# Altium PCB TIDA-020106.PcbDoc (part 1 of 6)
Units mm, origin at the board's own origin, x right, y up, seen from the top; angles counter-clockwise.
Board outline 158.53 x 83.25 mm, 6 copper layers (Top Layer, GND, Power, Sig4, GND (Mid4), Bottom Layer), stack 1.59 mm thick; 410 components, 255 nets, 1280 pads, 2405 vias.
Unrouted connection lines stored in the file: 294.
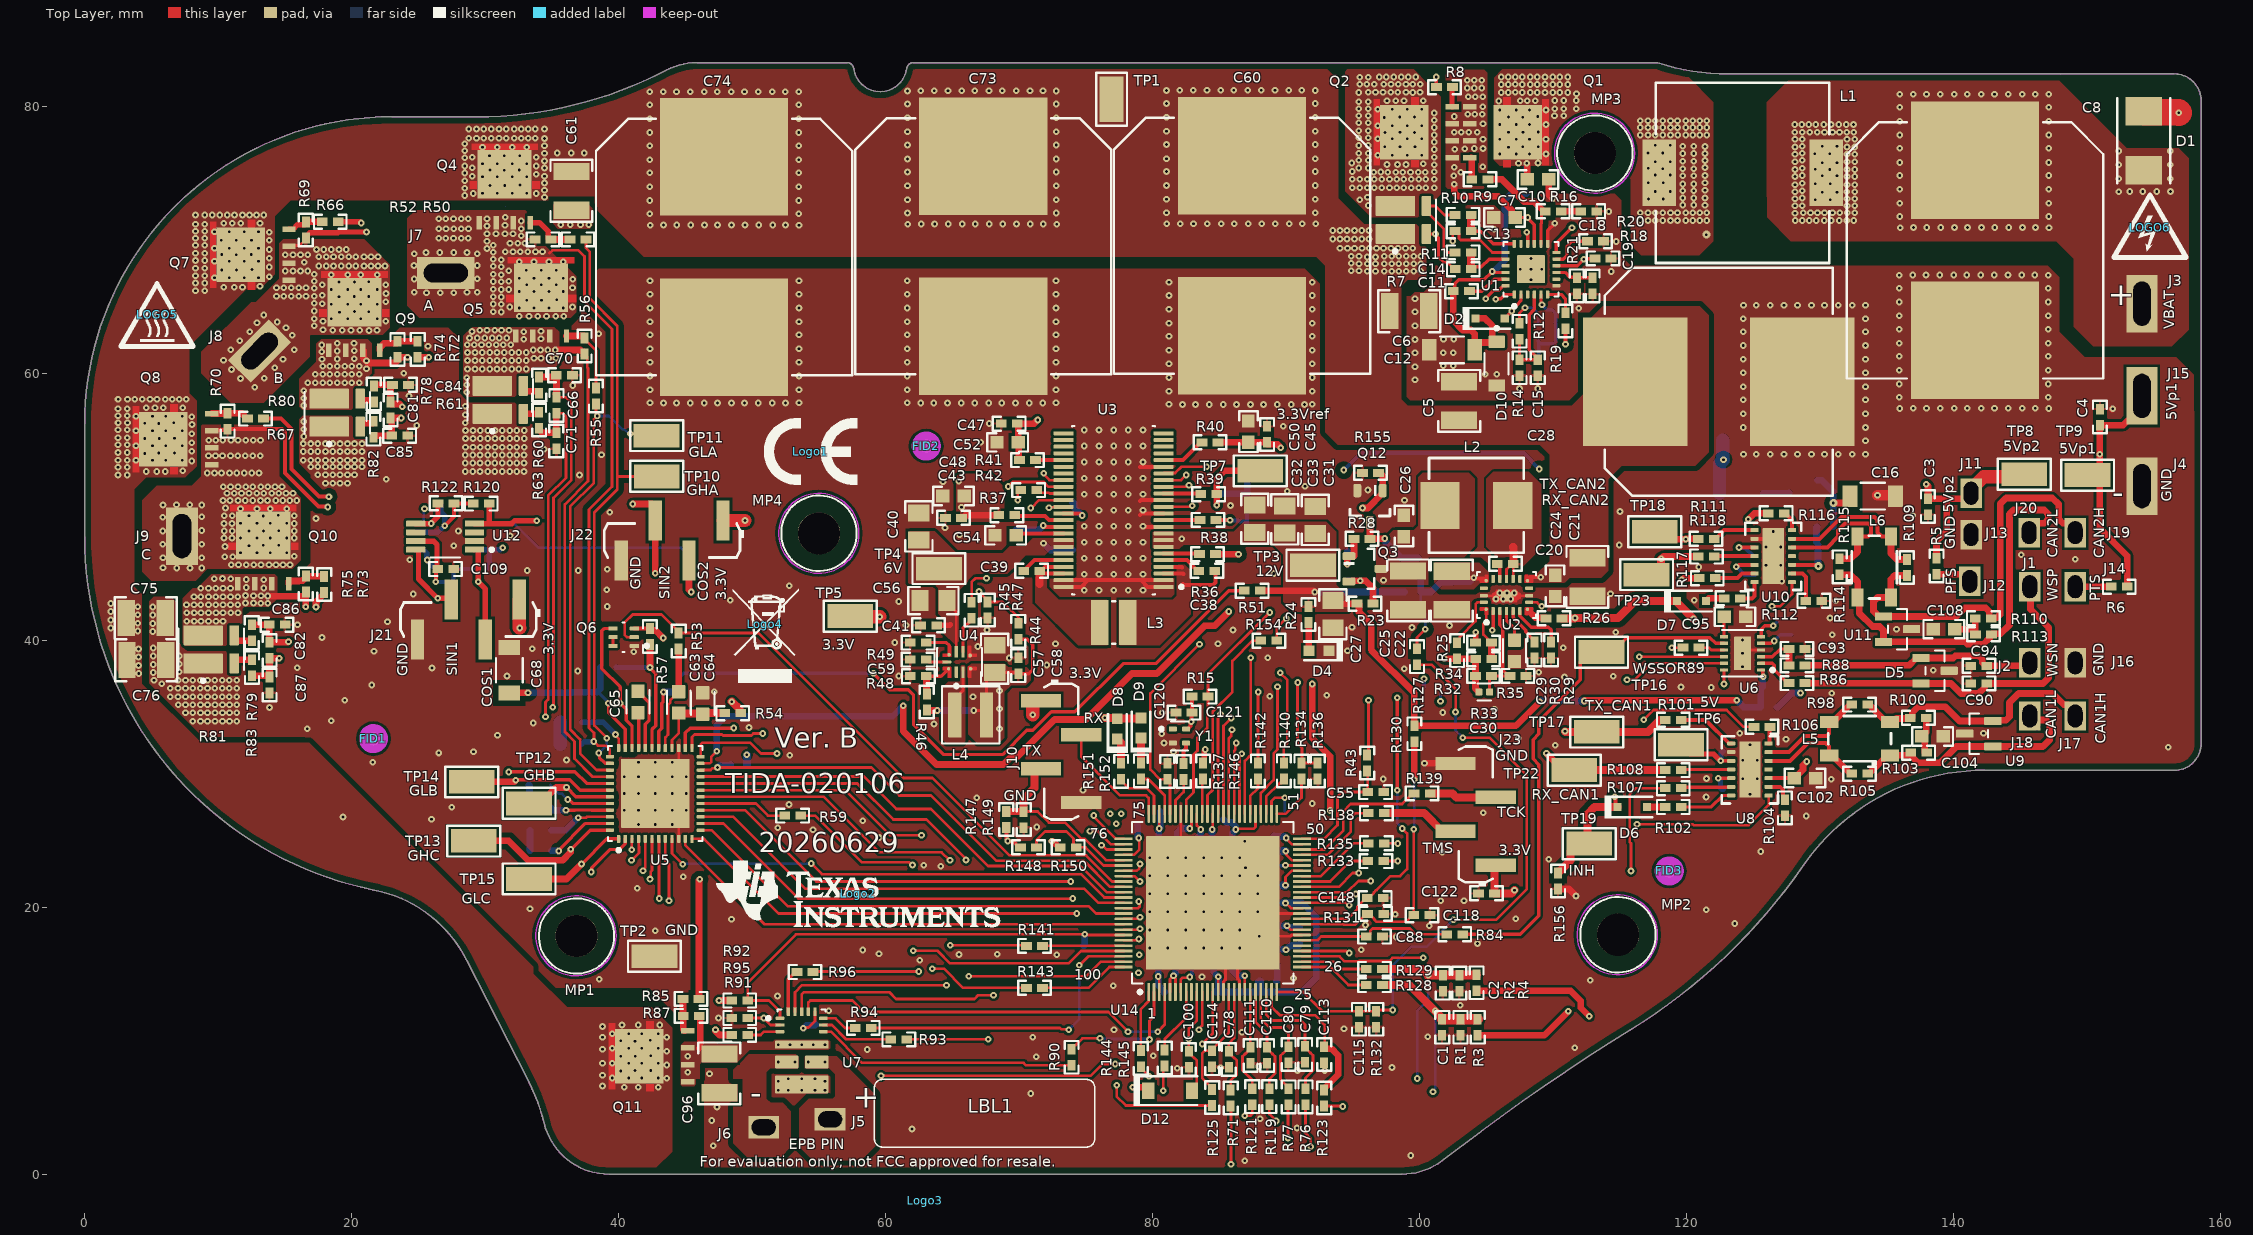
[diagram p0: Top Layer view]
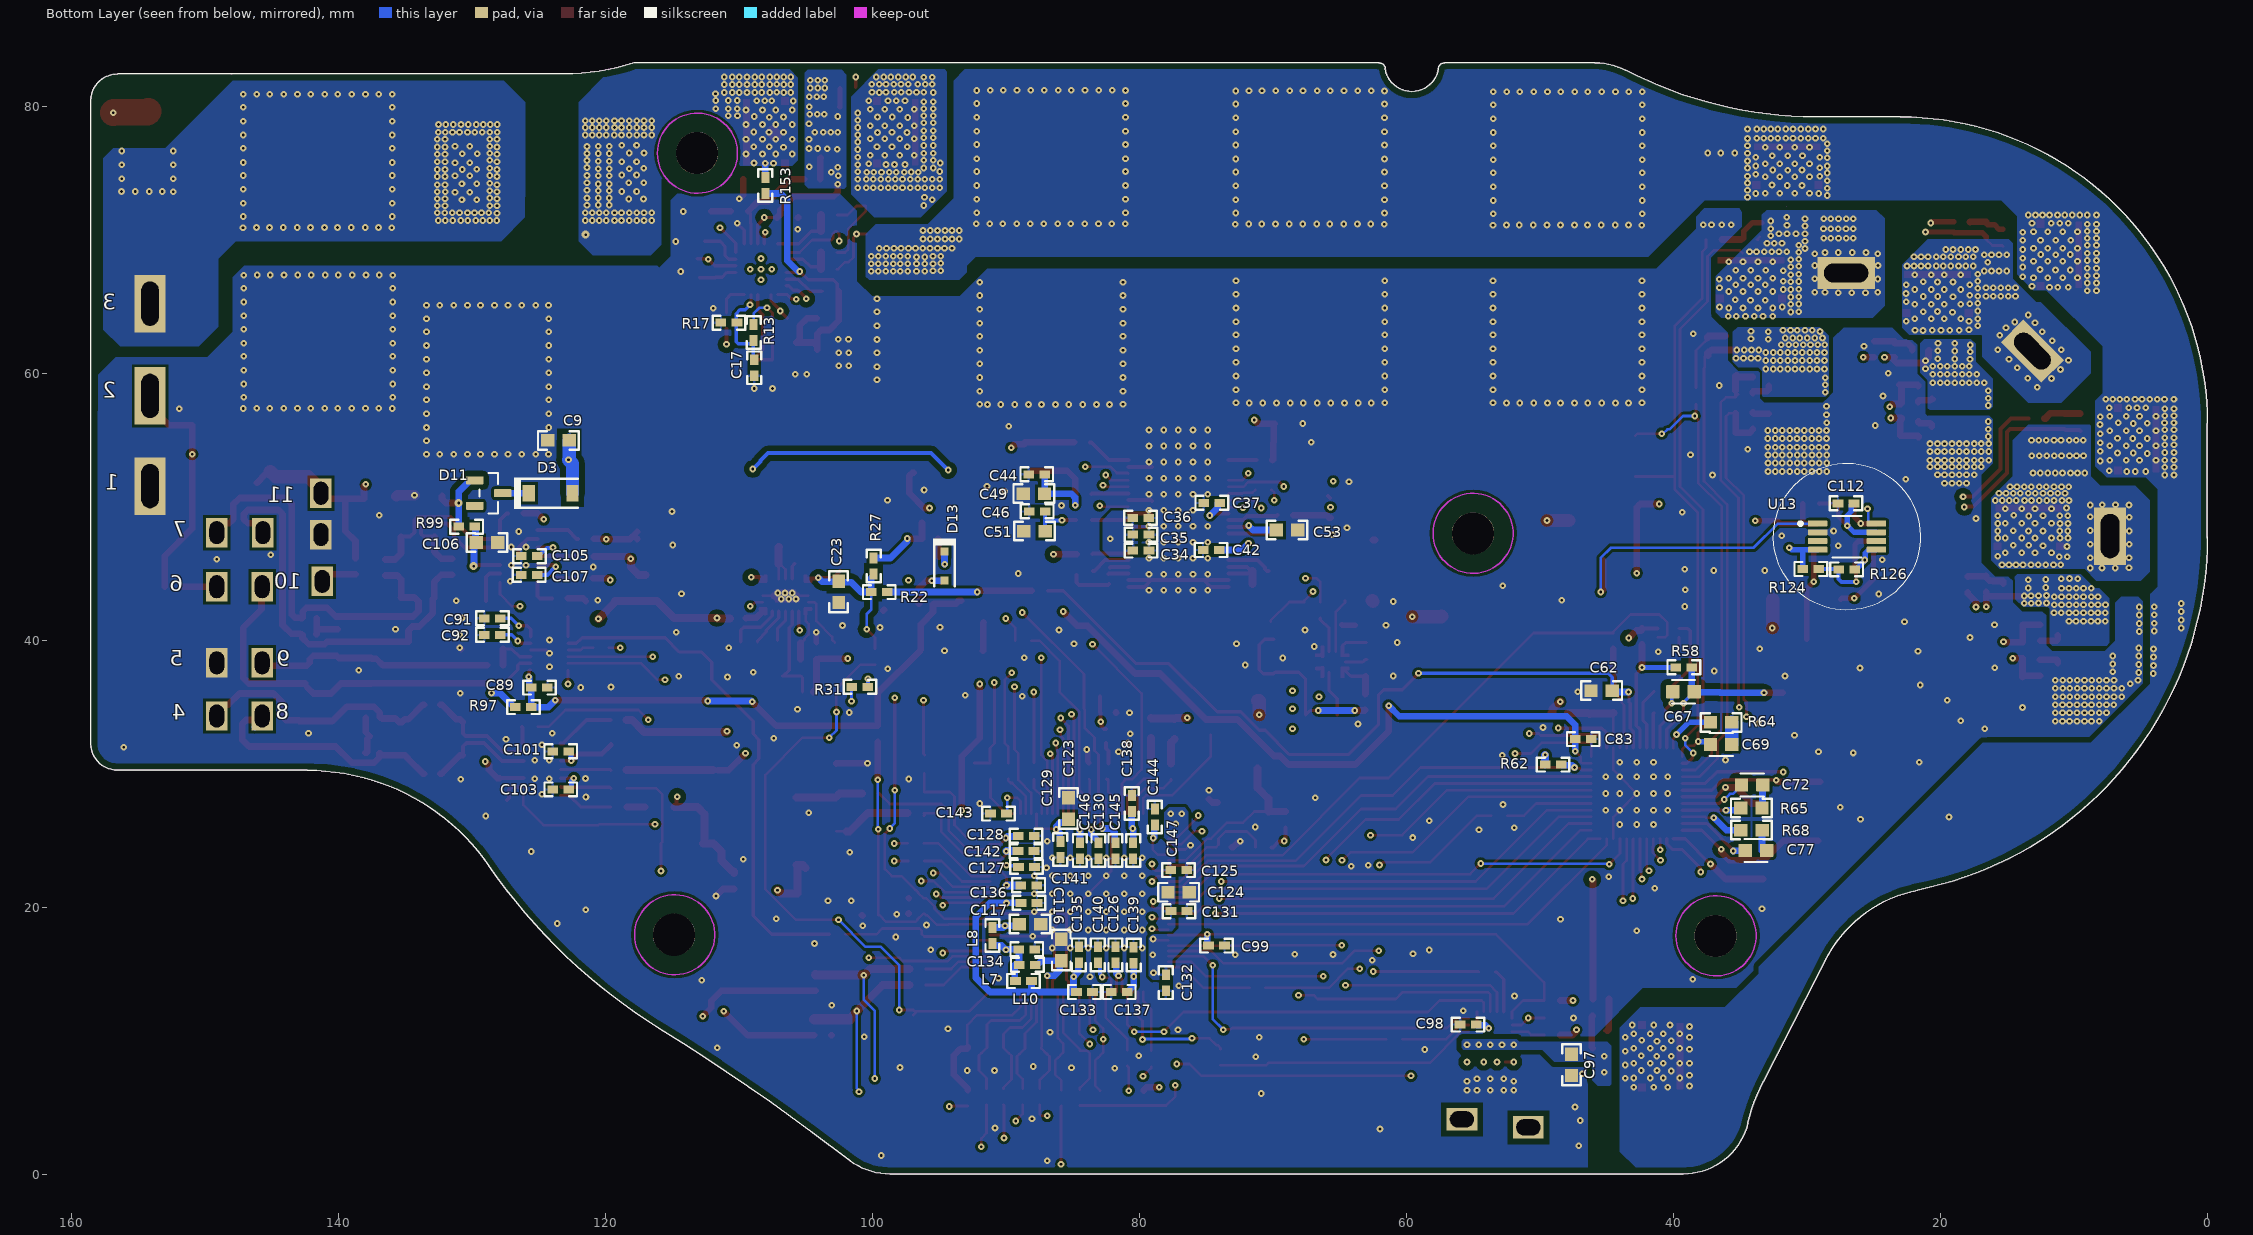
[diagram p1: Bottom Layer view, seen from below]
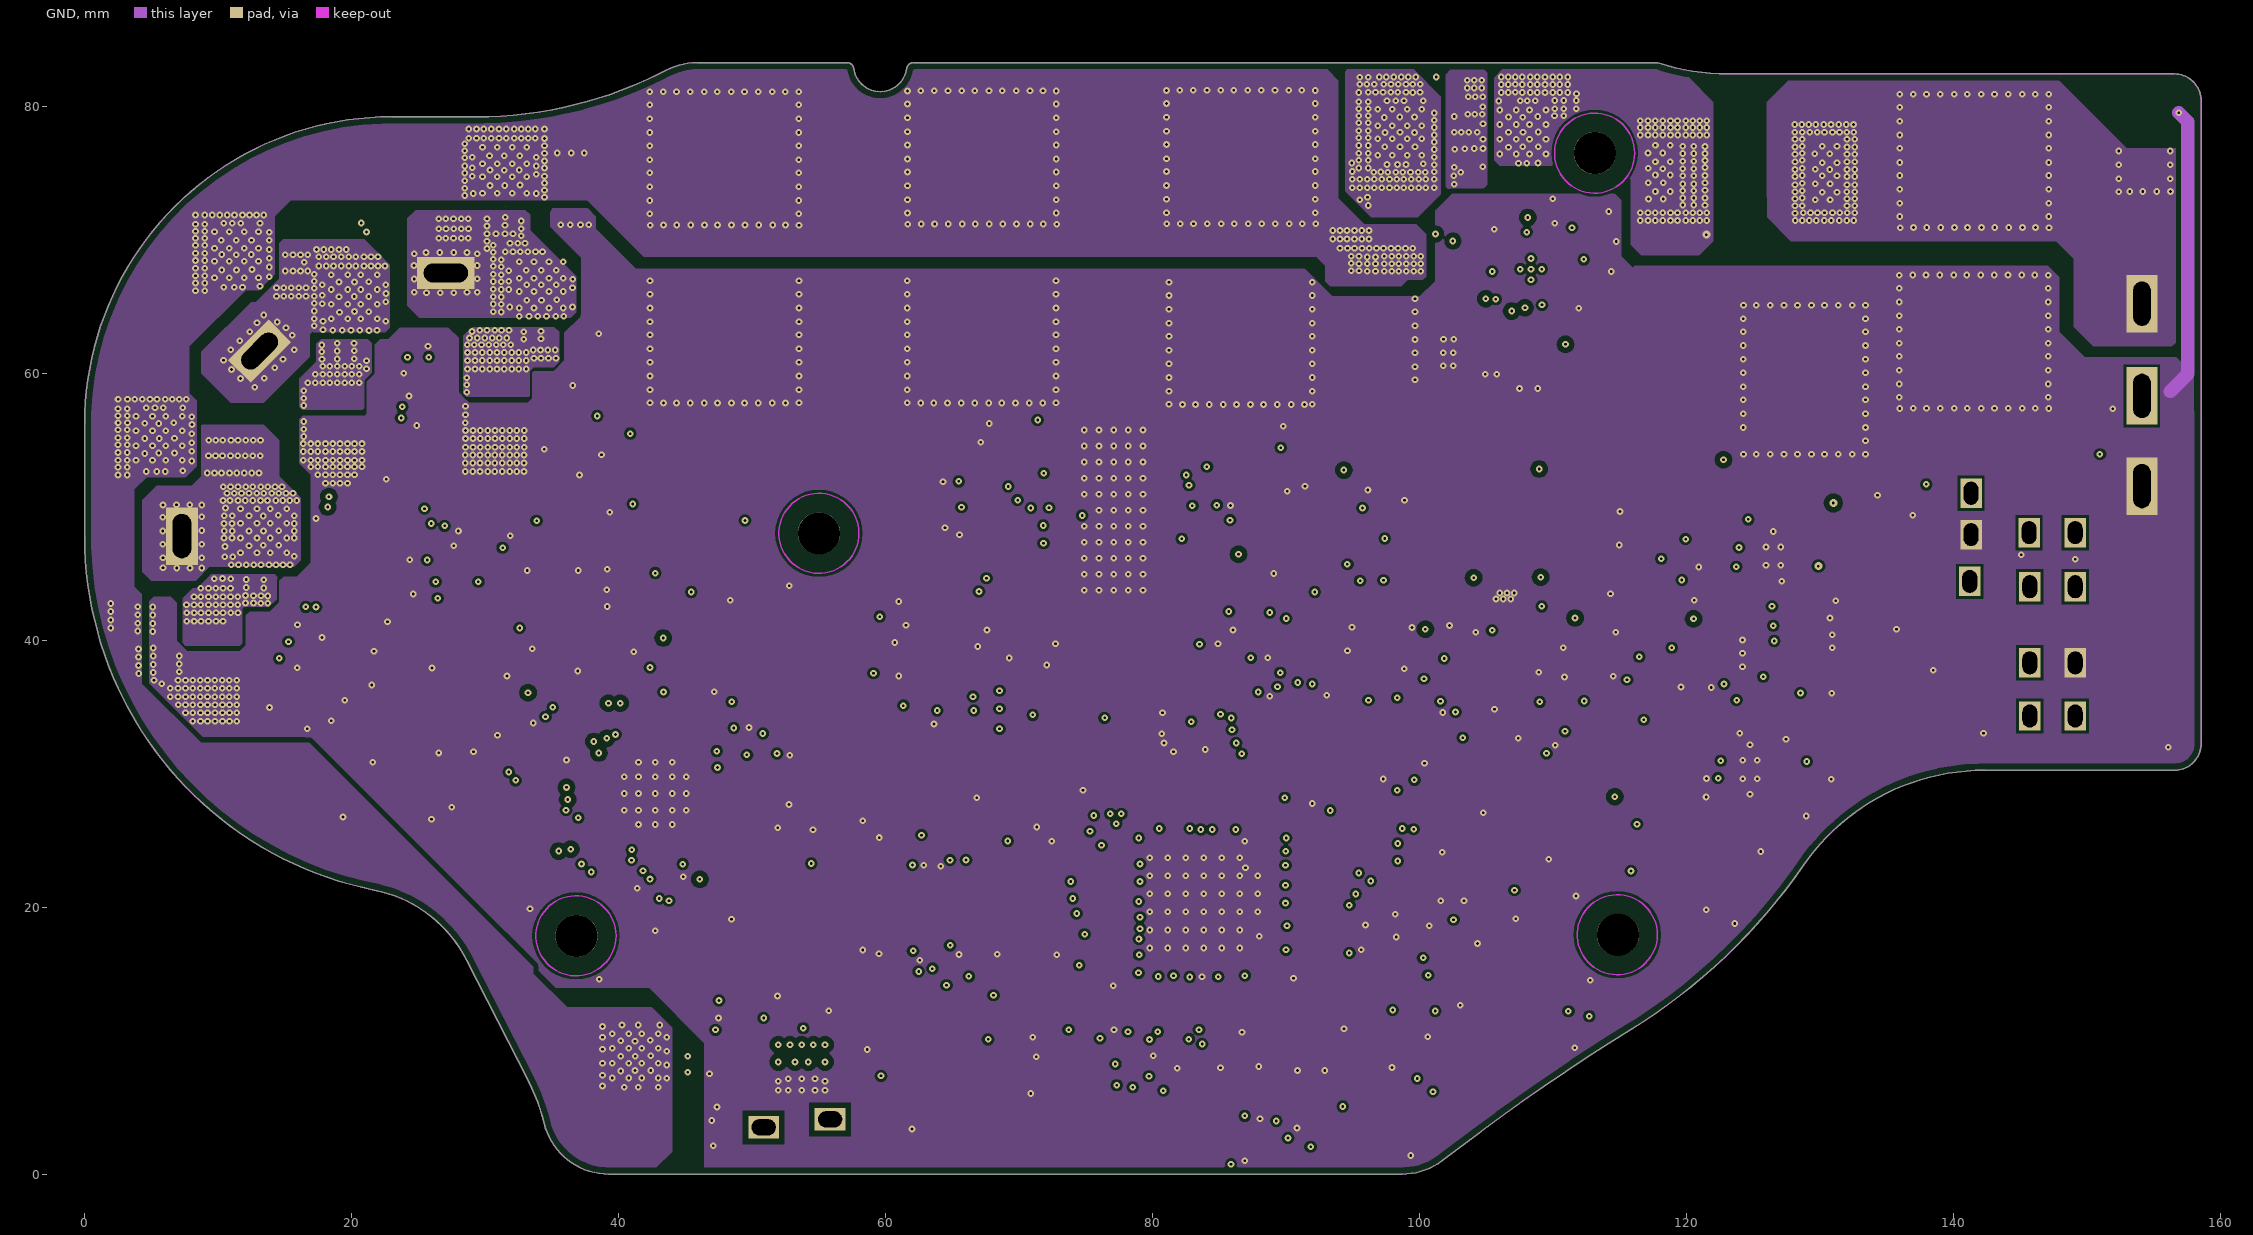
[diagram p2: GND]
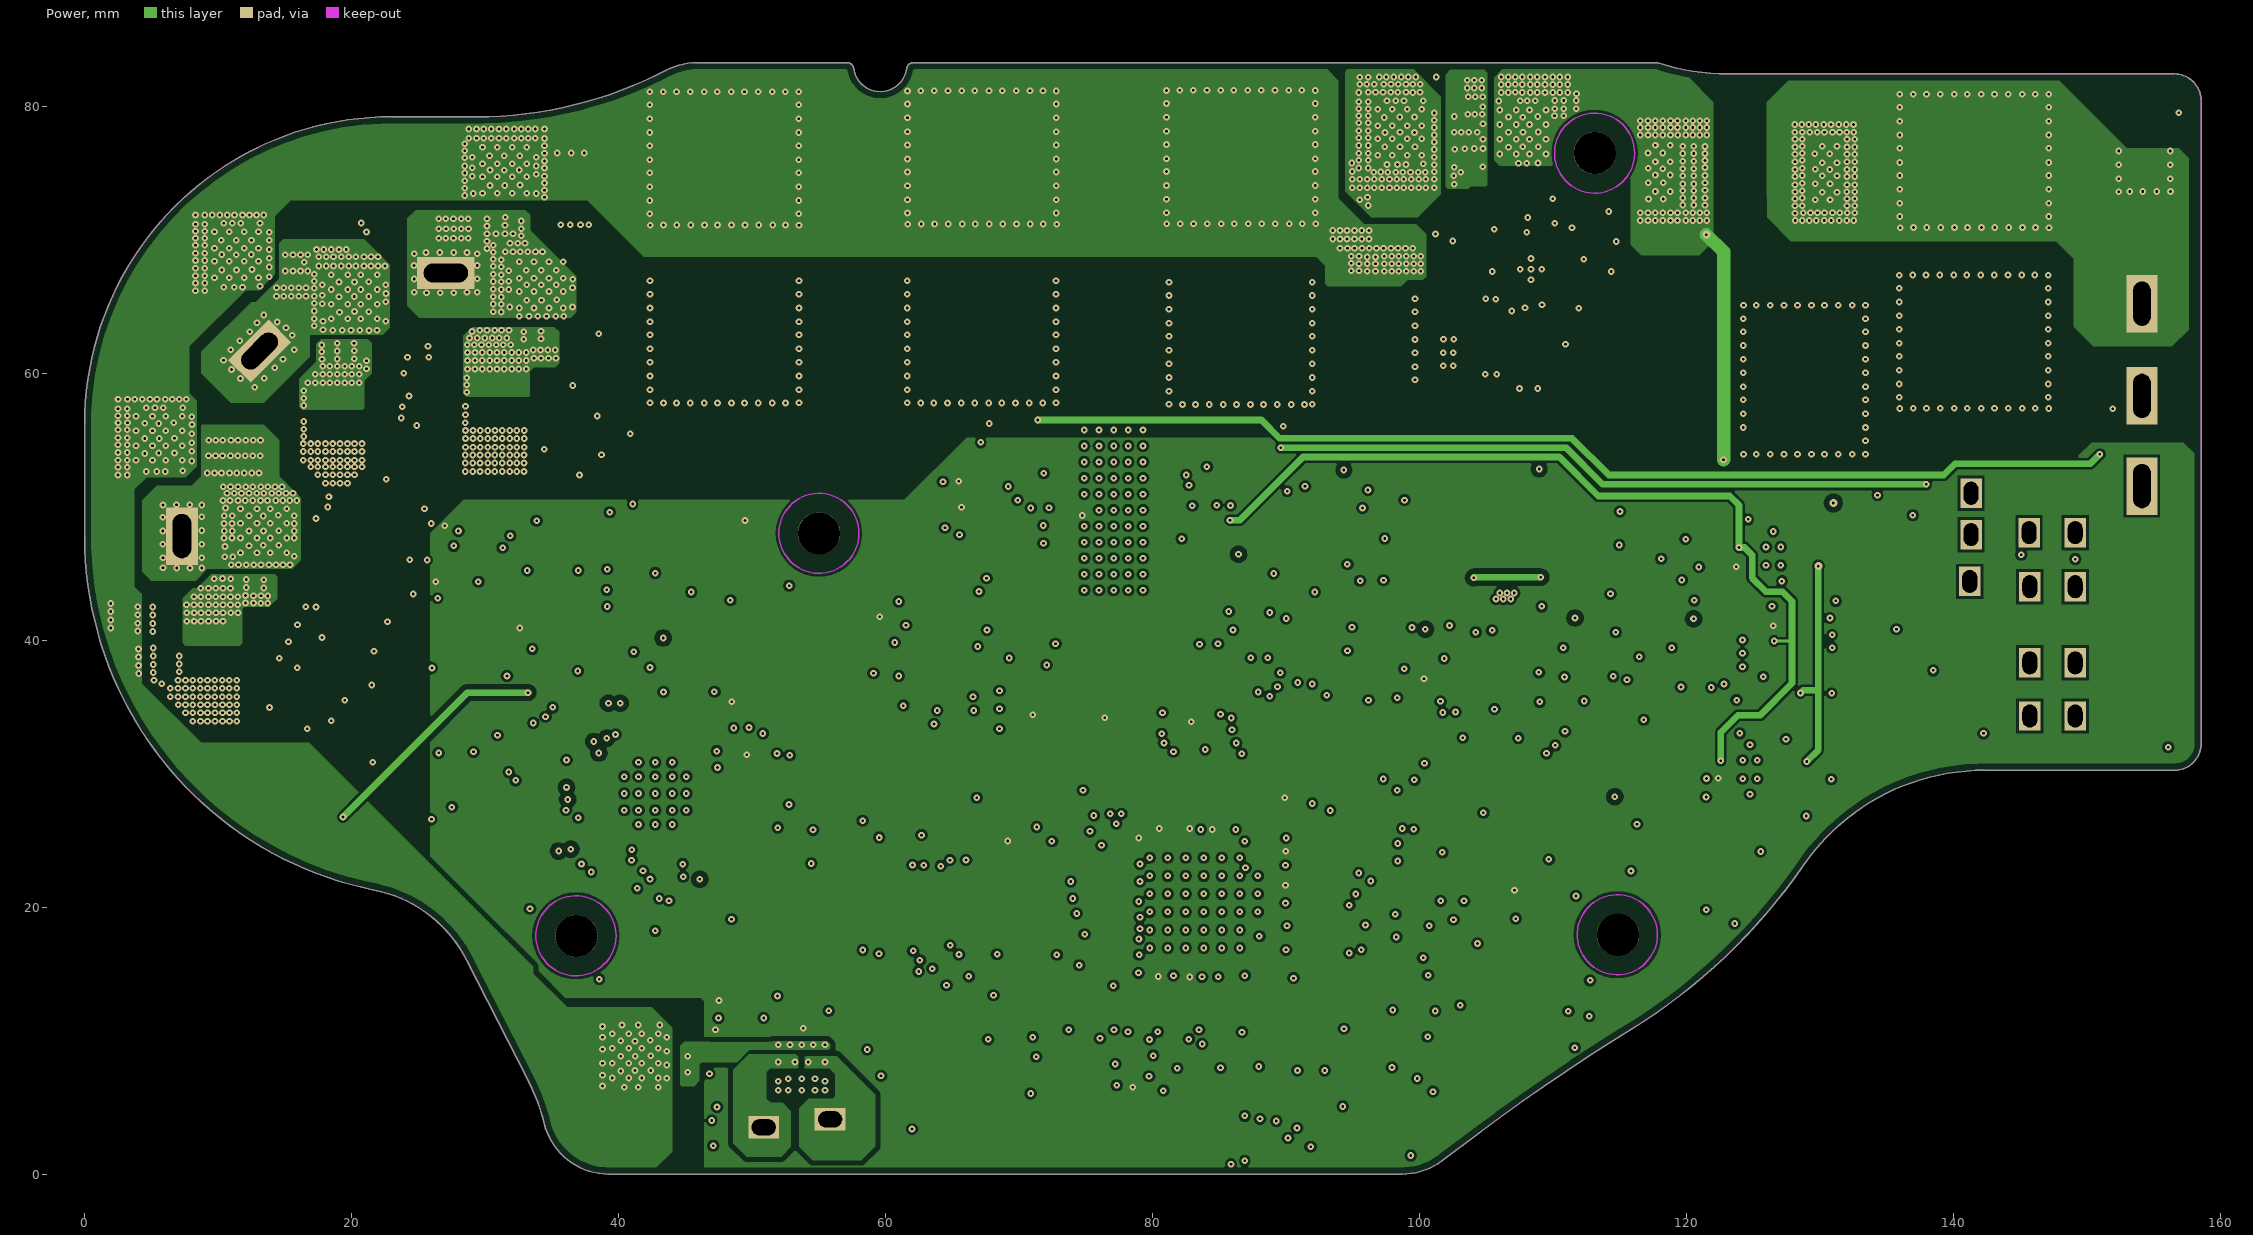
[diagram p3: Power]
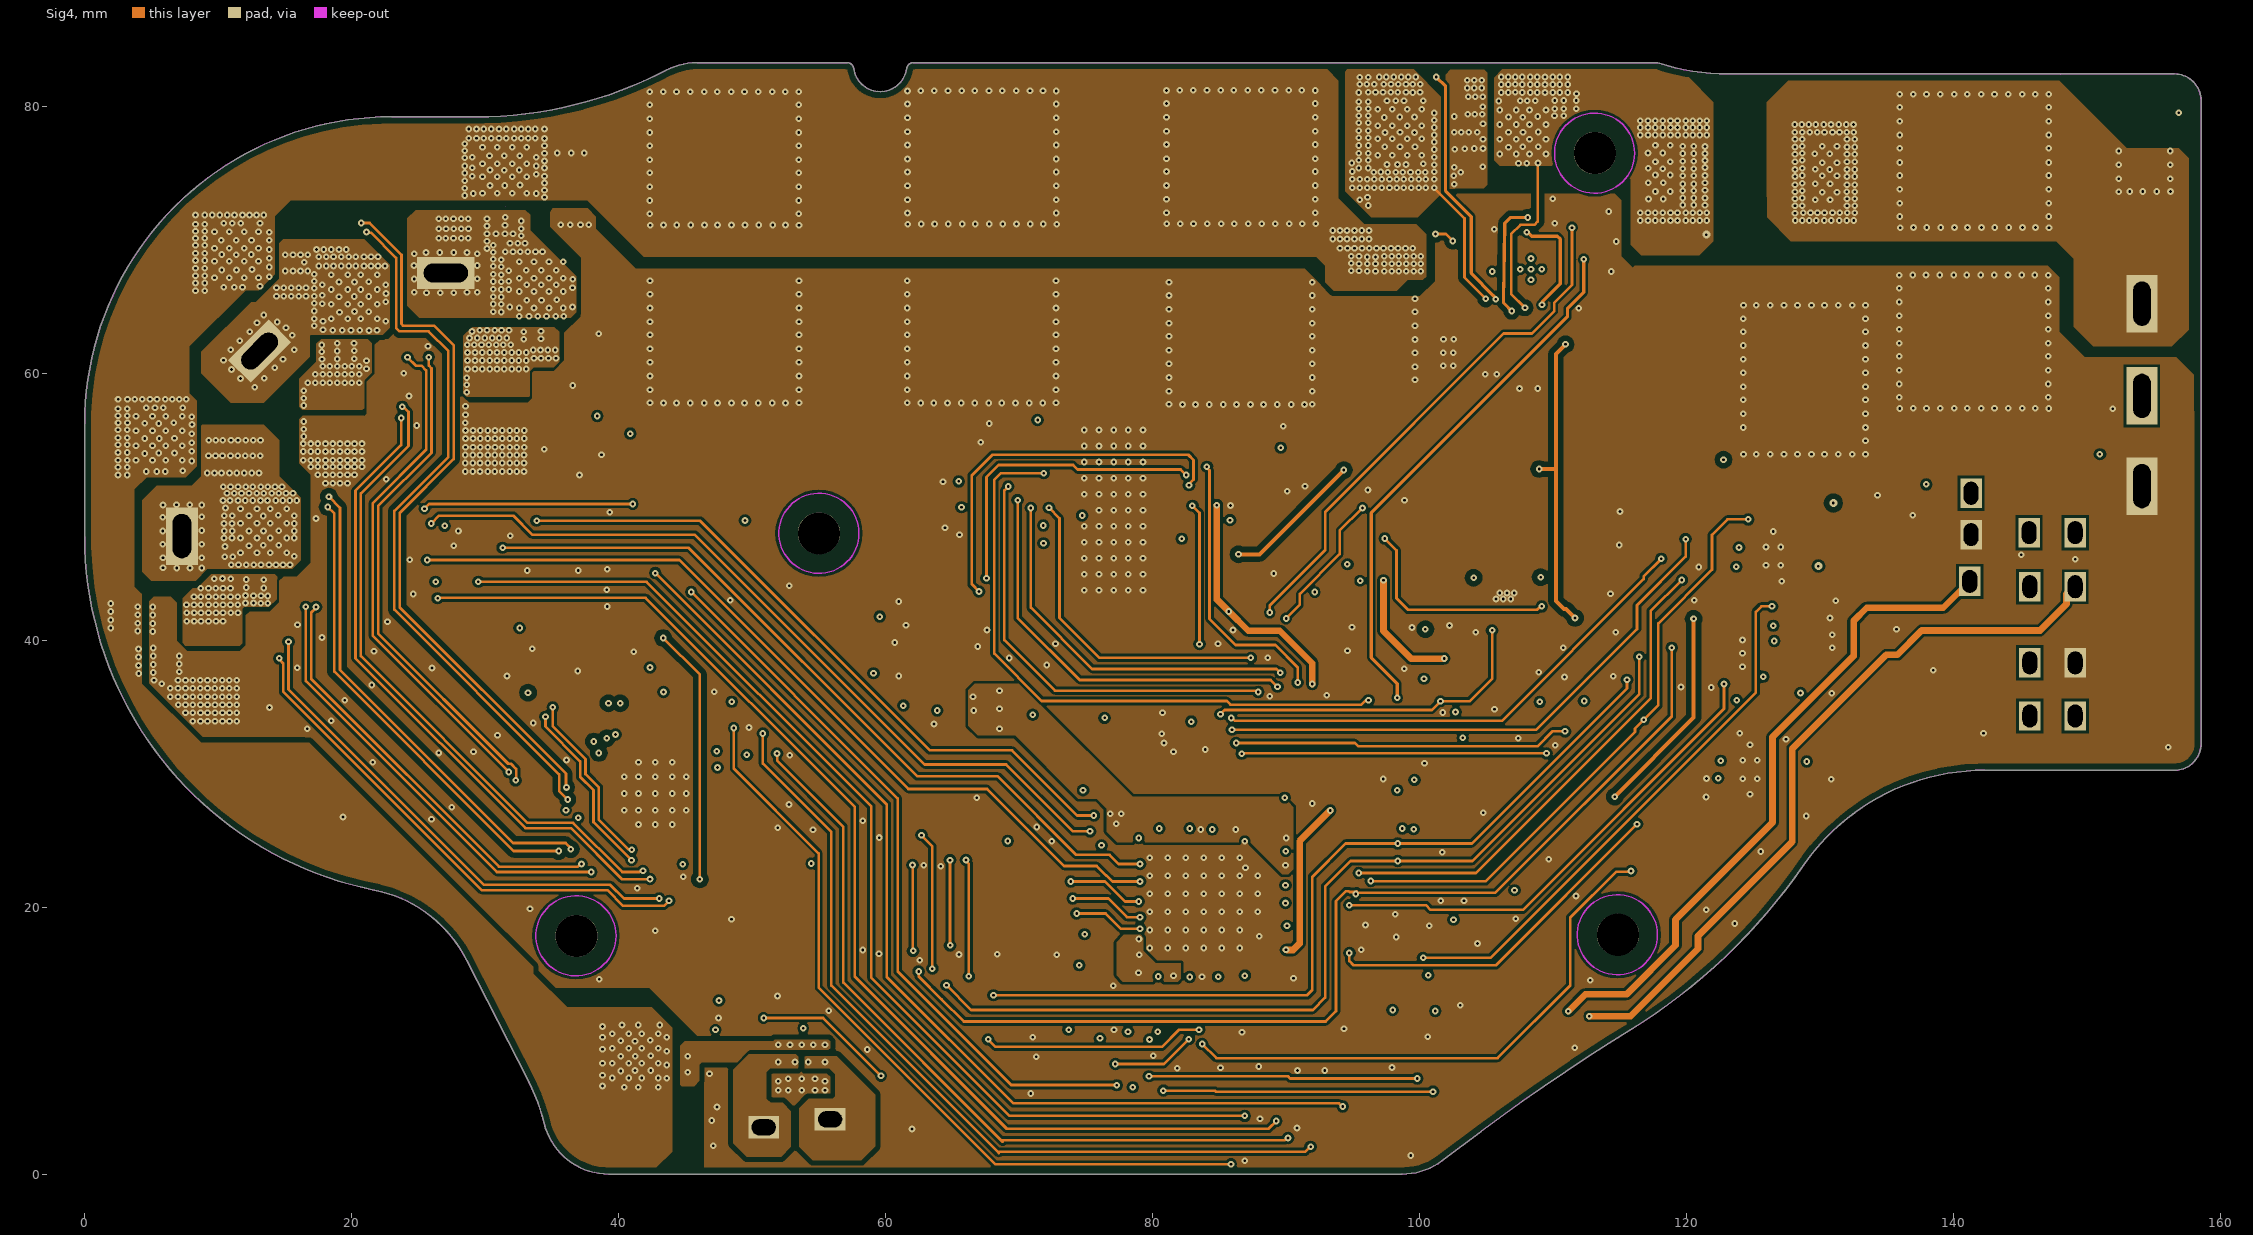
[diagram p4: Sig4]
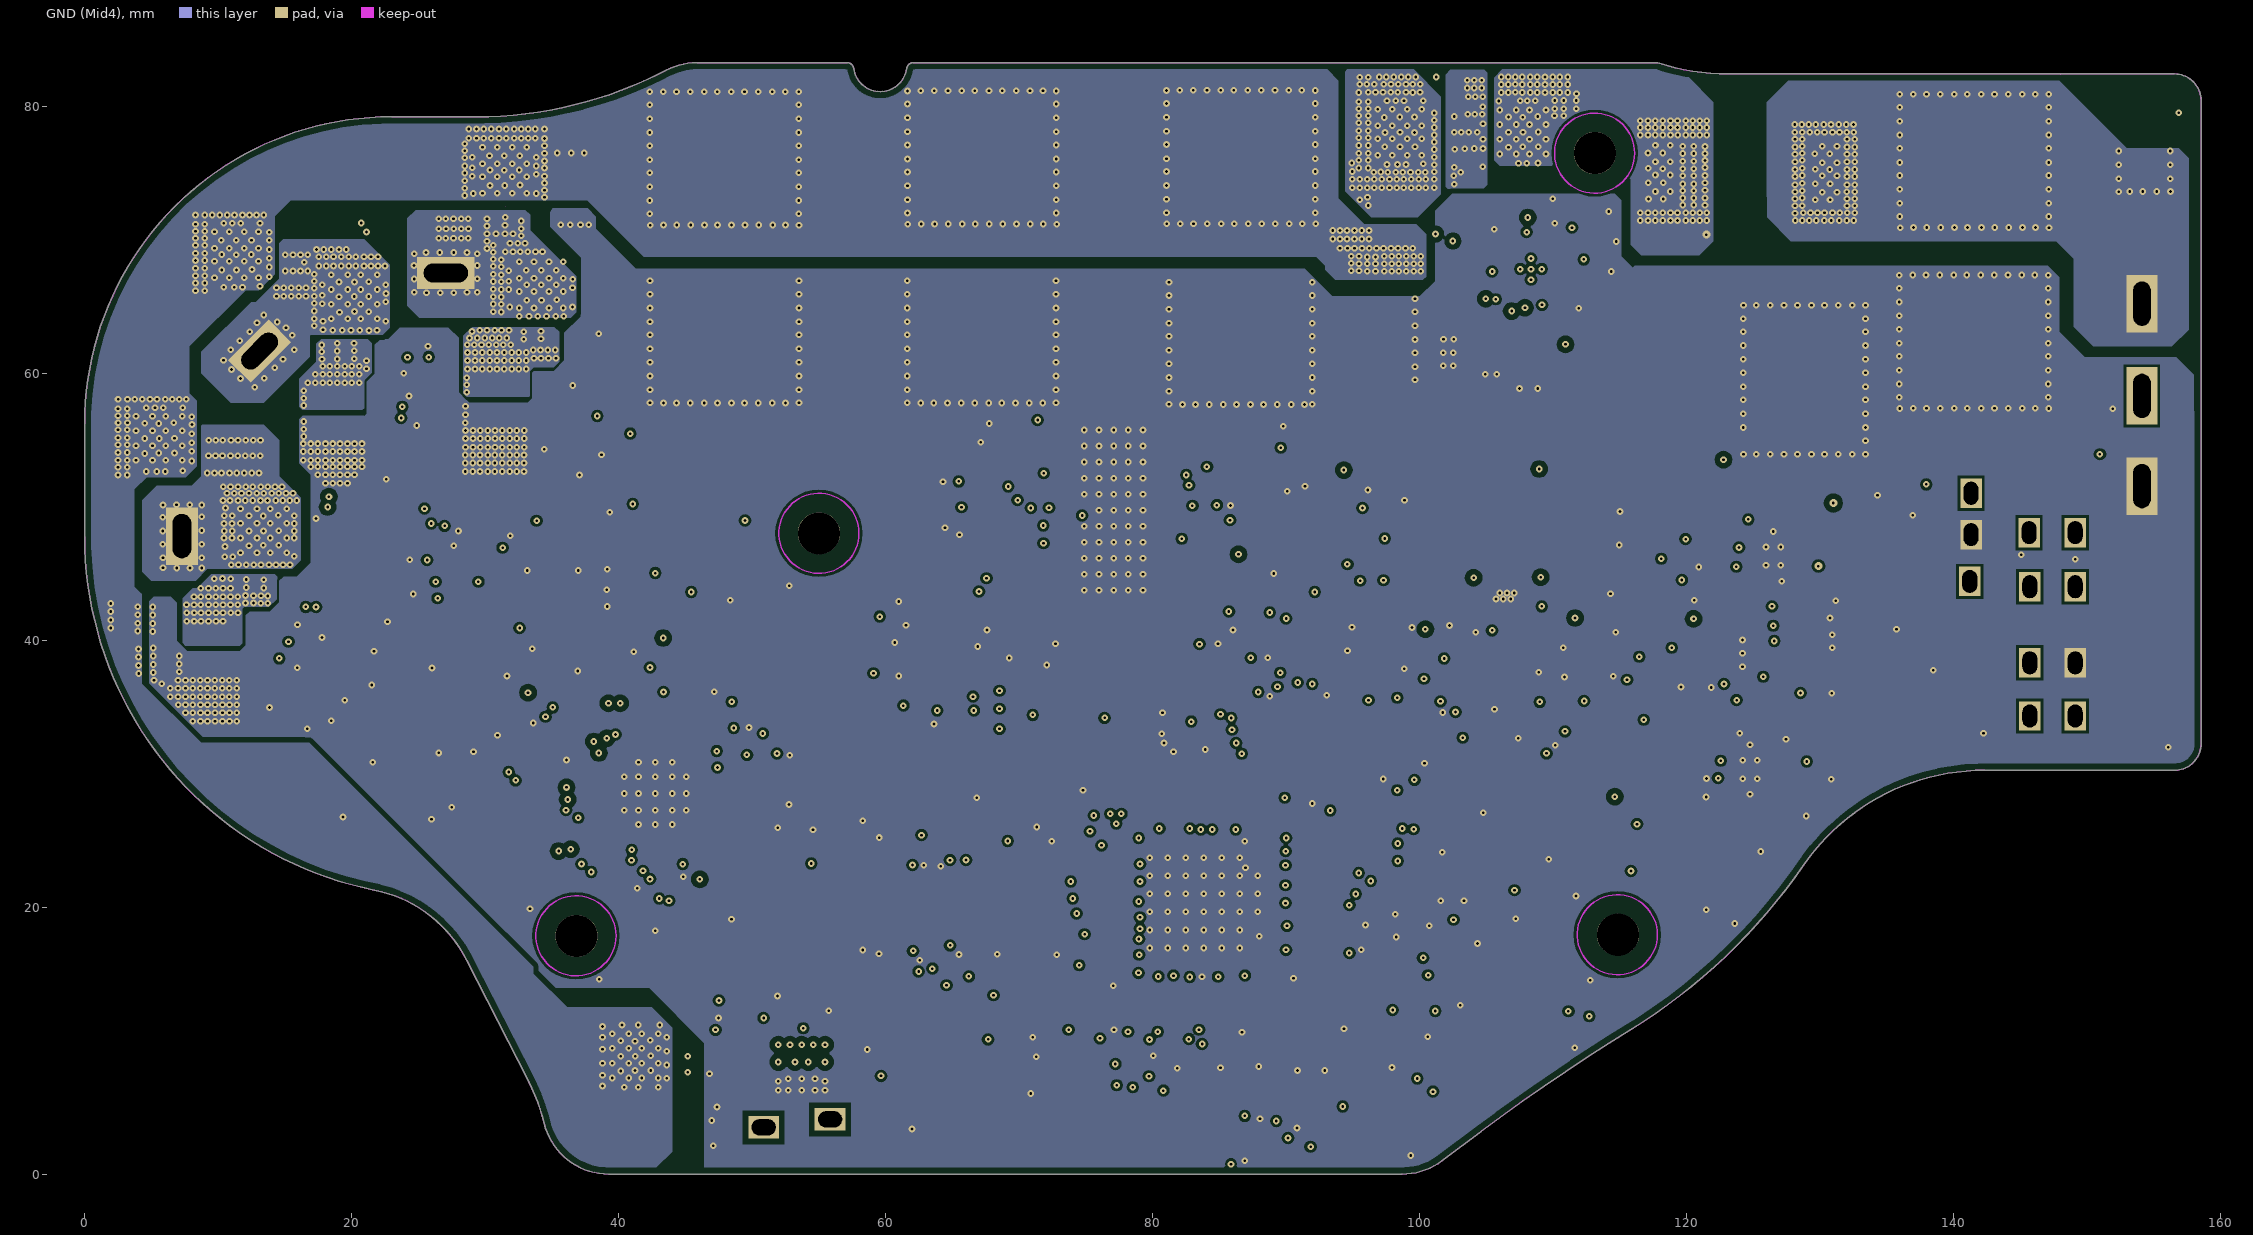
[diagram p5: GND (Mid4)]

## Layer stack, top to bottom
Top Solder: solder mask 0.01, Solder Resist, Dk 3.5
Top Layer: signal copper 0.035
Dielectric 1: prepreg 0.29, PP-006, Dk 4.1
GND: signal copper 0.0175
Dielectric 3: prepreg 0.29, PP-006, Dk 4.1
Power: signal copper 0.0175
Dielectric1: core 0.29, FR-4 High Tg, Dk 4.8
Sig4: signal copper 0.0175
Dielectric 4: prepreg 0.29, PP-006, Dk 4.1
GND (Mid4): signal copper 0.0175
Dielectric 2: prepreg 0.29, PP-006, Dk 4.1
Bottom Layer: signal copper 0.035
Bottom Solder: solder mask 0.01, Solder Resist, Dk 3.5

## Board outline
21.686,21.28 cw(c19.718,11.475) 28.628,16.015 33.253,6.938 cw(c20.408,0.395) 34.412,3.814 ccw(c39.269,5) 39.269,0 98.671,0 ccw(c98.671,5) 101.669,0.997 104.606,3.197 cw(c195.432,-118.089) 115.806,10.827 ccw(c93,47.752) 128.731,23.118 cw(c142.315,13.752) 142.315,30.252 156.533,30.252 ccw(c156.533,32.252) 158.533,32.252 158.533,80.41 ccw(c156.533,80.41) 156.533,82.41 123.125,82.41 cw(c123.125,99.41) 117.836,83.254 62.065,83.254 ccw(c62.065,82.754) 61.569,82.82 cw(c59.587,83.087) 59.587,81.087 cw(c59.587,83.087) 57.605,82.82 ccw(c57.109,82.754) 57.109,83.254 45.87,83.254 ccw(c45.87,78.254) 43.559,82.687 cw(c29.334,109.974) 29.334,79.202 23,79.202 ccw(c23,56.202) 0,56.226 0,56.202 0,47.752 ccw(c27,47.752)

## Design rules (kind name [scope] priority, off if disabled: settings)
AcuteAngle [All] p1: minimum=4.50000000000000E+0001 checktracksonly=FALSE
AssemblyTestPointUsage [All] p1: valid=2
BoardOutlineClearance BoardOutlineClearance_MountingHoles [OnCopper and InComponentClass('Mounting Holes')] p1: gap=0.5 ignorepadtopadclearanceinfootprint=FALSE
BoardOutlineClearance BoardOutlineClearance_Poly [OnCopper and IsPoly] p2: gap=0.5 ignorepadtopadclearanceinfootprint=FALSE
BoardOutlineClearance [OnCopper and Not InComponentClass('Logo') and not InComponentClass('FiducialMark') and not InRegion(1000,500,4000,800) and not InPoly] p3: gap=0.5 ignorepadtopadclearanceinfootprint=FALSE
Clearance Clearance_Keepouts [((IsTrack Or IsArc) And Not InPoly) And IsFree and IsKeepOut vs ((IsTrack Or IsArc) And Not InPoly) And IsFree and IsKeepOut] p1: gap=0 ignorepadtopadclearanceinfootprint=FALSE
Clearance Clearance_FiducialMark [IsKeepOut and InComponentClass('FiducialMark') vs IsPad and InComponentClass('FiducialMark')] p2: gap=0 ignorepadtopadclearanceinfootprint=FALSE
Clearance 48V_GND [InNetClass('48V') vs InNetClass('GND')] p3: gap=0.4 ignorepadtopadclearanceinfootprint=TRUE
Clearance [All] p4: gap=0.2 ignorepadtopadclearanceinfootprint=TRUE
ComponentClearance ComponentClearance_MountingHoles_FiducialMarks [InComponentClass('Mounting Holes') vs InComponentClass('FiducialMark')] p1: gap=1.27 collisioncheckmode=3 verticalgap=0.254 showdistances=FALSE
ComponentClearance ComponentClearance_Shunt [InComponentClass('Header') vs InComponentClass('Shunt')] p2: gap=0 collisioncheckmode=3 verticalgap=0 showdistances=FALSE
ComponentClearance ComponentClearance_Logo [InComponentClass('Logo')] p3: gap=0.762 collisioncheckmode=3 verticalgap=0.254 showdistances=FALSE
ComponentClearance ComponentClearance_ScrewToNut [(HasFootprint('NY PMS 440 0025 PH')) vs (HasFootprint('Keystone_1902C'))] p4: gap=0.127 collisioncheckmode=3 verticalgap=0.254 showdistances=FALSE
ComponentClearance ComponentClearance_MountingHoles [InComponentClass('Mounting Holes')] p5: gap=2.54 collisioncheckmode=3 verticalgap=2540 showdistances=FALSE
ComponentClearance ComponentClearance_SmallPassives [HasFootprint('0201*') or HasFootprint('0402*') or HasFootprint('0508') or HasFootprint('0603*') or HasFootprint('0612') or HasFootprint('0805*') or HasFootprint('0815*') or HasFootprint('0830*') or HasFootprint('1206*') or HasFootprint('1210*') or HasFootprint('1808*') or HasFootprint('1812*') or HasFootprint('1825*') or HasFootprint('2010*') or HasFootprint('2220*') or HasFootprint('2225*') or HasFootprint('2512*') or HasFootprint('2728*') or HasFootprint('3518*') vs HasFootprint('0201*') or HasFootprint('0402*') or HasFootprint('0508') or HasFootprint('0603*') or HasFootprint('0612') or HasFootprint('0805*') or HasFootprint('0815*') or HasFootprint('0830*') or HasFootprint('1206*') or HasFootprint('1210*') or HasFootprint('1808*') or HasFootprint('1812*') or HasFootprint('1825*') or HasFootprint('2010*') or HasFootprint('2220*') or HasFootprint('2225*') or HasFootprint('2512*') or HasFootprint('2728*') or HasFootprint('3518*')] p6: gap=0.38 collisioncheckmode=3 verticalgap=0.254 showdistances=FALSE
ComponentClearance ComponentClearance_THtoSMT [IsThruComponent vs IsSMTComponent] p7: gap=0.762 collisioncheckmode=3 verticalgap=0.762 showdistances=FALSE
ComponentClearance ComponentClearance_THtoTH [IsThruComponent vs IsThruComponent] p8: gap=0.508 collisioncheckmode=3 verticalgap=0.762 showdistances=FALSE
ComponentClearance [All] p9: gap=0.108 collisioncheckmode=3 verticalgap=0.254 showdistances=FALSE
DiffPairsRouting [All] p1: maxlimit=2.54 minlimit=0.254 mostfreqgap=0.254 toplayer_minwidth=0.381 toplayer_maxwidth=0.381 toplayer_prefwidth=0.381 midlayer1_minwidth=0.381 midlayer1_maxwidth=0.381 midlayer1_prefwidth=0.381 midlayer2_minwidth=0.381 midlayer2_maxwidth=0.381 midlayer2_prefwidth=0.381 midlayer3_minwidth=0.381 midlayer3_maxwidth=0.381 midlayer3_prefwidth=0.381 midlayer4_minwidth=0.381 midlayer4_maxwidth=0.381 midlayer4_prefwidth=0.381 bottomlayer_minwidth=0.381 bottomlayer_maxwidth=0.381 bottomlayer_prefwidth=0.381 maxuncoupledlength=25.4
FabricationTestPointUsage TestPointUsage [All] p1: valid=2 allowmultiple=FALSE
FabricationTestpoint Testpoint [All] p1: side=3 testpointundercomponent=TRUE minsize=1.016 maxsize=2.54 preferedsize=1.524 minholesize=0 maxholesize=1.016 preferedholesize=0.813 testpointgrid=0.025 allowsidetop=TRUE allowsidebottom=TRUE usegrid=TRUE gridtolerance=0
FanoutControl Fanout_LCC [IsLCC] p1: bgadir=Out bgaviamode=Centered fanoutstyle=Auto fanoutdirection=Alternating viagrid=0.025 // Fanout_LCC (Default Rule)
FanoutControl Fanout_BGA [IsBGA] p2: bgadir=Out bgaviamode=Centered fanoutstyle=Auto fanoutdirection=Alternating viagrid=0.025 // Fanout_BGA (Default Rule)
FanoutControl Fanout_Default [All] p4: bgadir=Out bgaviamode=Centered fanoutstyle=Auto fanoutdirection=Alternating viagrid=0.025 // Fanout_Default (Default Rule)
FanoutControl Fanout_Small [(CompPinCount < 5)] p5: bgadir=Out bgaviamode=Centered fanoutstyle=Auto fanoutdirection=OutThenIn viagrid=0.025 // Fanout_Small (Default Rule)
HoleSize [All] p1: absolutevalues=TRUE maxlimit=6.375 minlimit=0.2 maxpercent=80.000 minpercent=20.000
MinimumAnnularRing MinimumAnnularRing_ThermalPadVias [IsVia and InAnyComponent] p1: minimumring=0.15
MinimumSolderMaskSliver MinimumSolderMaskSliver_Logo [InComponentClass('Logo') vs InComponentClass('Logo')] p1: minsoldermaskwidth=0.018
MinimumSolderMaskSliver [All] p2: minsoldermaskwidth=-1
PlaneConnect [All] p1: planeconnectstyle=Direct reliefexpansion=0.254 reliefentries=4 reliefconductorwidth=0.5 reliefairgap=0.254
PolygonConnect 0402 [HasFootprint('0402')] p1: connectstyle=Relief reliefconductorwidth=0.2 reliefentries=4 polygonreliefangle="90 Angle" airgapwidth=0.2
PolygonConnect [All] p2: connectstyle=Direct reliefconductorwidth=0.5 reliefentries=4 polygonreliefangle="90 Angle" airgapwidth=0.254
RoutingVias ThermalPadVias [IsVia and InAnyComponent] p1: holewidth=0.2 width=0.5 viastyle="Through Hole" minholewidth=0.2 minwidth=0.5 maxholewidth=0.33 maxwidth=0.6
RoutingVias [All] p2: holewidth=0.2 width=0.5 viastyle="Through Hole" minholewidth=0.2 minwidth=0.5 maxholewidth=2 maxwidth=3
SilkToBoardRegionClearance [Not ((IsComment or IsDesignator) And (Hide <> 'False')) and not InRegion(1000,500,4000,800)] p1:
SilkToSilkClearance SilkToSilkClearance_Pb-FreeLogo [(HasFootprint('Pb-Free_Overlay_Medium') OR HasFootprint('Pb-Free_Overlay_Small')) vs (HasFootprint('Pb-Free_Overlay_Medium') OR HasFootprint('Pb-Free_Overlay_Small'))] p1: silktosilkclearance=0
SilkToSilkClearance [All] p2: silktosilkclearance=0
SilkToSolderMaskClearance SilkToComponentPadClearance [(IsPad or IsFill or IsRegion) and InAnycomponent] p1: minsilkscreentomaskgap=-1 clearancetoexposedcopper=TRUE
SilkToSolderMaskClearance "Silk to Solder Mask Opening" [All] p2: minsilkscreentomaskgap=-1 clearancetoexposedcopper=FALSE
SolderMaskExpansion [All] p1: expansion=0.05 istentingtop=FALSE
UnRoutedNet [All] p1: checkbadconnections=TRUE
UnpouredPolygon [All] p1: allowunpoured=TRUE allowshelved=TRUE
Width [All] p1: maxlimit=2.54 minlimit=0.152 preferedwidth=0.254 checkconnectedcopper=TRUE
13 further rules are at their usual default settings.

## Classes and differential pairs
net class GND: 1.25V 1.25V_EN 1.25V_VMON1 3.3V 3.3Vref 5V 5Vp1 5Vp2 12V 12V_Cobra CLK_PMIC FB GND INH_CAN MCU_ERRORSTS MOS_LM68645 NetC38_1 NetC38_2 NetC39_1 NetC39_2 NetC53_2 NetC54_2 NetC59_2 NetD4_1 NetD13_1 NetD13_2 NetL4_1 NetQ12_1 NetQ12_3 NetR36_2 NetR37_2 NetR38_2 NetR39_2 NetR40_2 NetR41_2 NetR42_2 NetR43_1 NetR45_1 NetR46_1 NetR49_2 NetR146_1 nSCS_PMIC nXRS_DSP PMIC_DIAG_OUT SDI_PMIC SDO_PMIC SW_U4 VCC_6V0 VDDA_3V3 VSNS
net class 48V: 48V/12V_BDC 48V/12V_C 48V/12V_IN 48V/12V_IN_FILTERED 48V/12V_P Cutoff_EPB GHA GHB GHC INH_CAN NetC7_2 NetC13_2 NetC67_1 NetQ2_5 NetR7_4 NetR9_1 OUTA_EPB OUTB_EPB SHA SHB SHC
component class U_GPIO_Power: C123 C124 C125 C126 C127 C128 C129 C130 C131 C132 C133 C134 C135 C136 C137 C138 C139 C140 C141 C142 C143 C144 C145 C146 C147 D8 D9 L10 R140 R141 R142 R143 R144 R145 R146 R147 R148 R149 R150 R151 R152
component class U_DC_DC: C20 C21 C22 C23 C24 C25 C26 C27 C28 C29 C30 D4 D13 L2 Q3 Q12 R22 R23 R24 R25 R26 R27 R28 R29 R30 R31 R32 R33 R34 R35 R154 R155 TP3 U2
component class U_Clock_Reset: C120 C121 C122 J23 R133 R134 R135 R136 R137 R138 R139 Y1
component class U_ADC: C116 C117 C118 L7 L8 R128 R129 R130 R131 U14
component class Sensor: ` C109 C110 C111 C112 C113 C114 J21 J22 R119 R120 R121 R122 R123 R124 R125 R126 U12 U13
component class PMIC: C31 C32 C33 C34 C35 C36 C37 C38 C39 C40 C41 C42 C43 C44 C45 C46 C47 C48 C49 C50 C51 C52 C53 C54 C55 C56 C57 C58 C59 L3 L4 R36 R37 R38 R39 R40 R41 R42 R43 R44 R45 R46 R47 R48 R49 TP4 TP5 TP6 TP7 TP8 TP9 U3 U4
component class Main: C1 C2 C3 C4 J1 J2 J3 J4 J5 J6 J7 J8 J9 J10 J11 J12 J13 J14 J15 J16 J17 J18 J19 J20 R1 R2 R3 R4 R5 R6
component class "Ideal Diode": C5 C6 C7 C8 C9 C10 C11 C12 C13 C14 C15 C16 C17 C18 C19 C115 C148 D1 D2 D3 D10 D11 L1 Q1 Q2 R7 R8 R9 R10 R11 R12 R13 R14 R15 R16 R17 R18 R19 R20 R21 R127 R132 R153 TP1 TP2 U1
component class Header: ` J10 J21 J22 J23
component class EPB: C88 C89 C90 C91 C92 C93 C94 C95 C96 C97 C98 C99 C100 D5 D12 Q11 R84 R85 R86 R87 R88 R89 R90 R91 R92 R93 R94 R95 R96 TP16 U6 U7
component class CAN: C101 C102 C103 C104 C105 C106 C107 C108 D6 D7 L5 L6 R97 R98 R99 R100 R101 R102 R103 R104 R105 R106 R107 R108 R109 R110 R111 R112 R113 R114 R115 R116 R117 R118 R156 TP17 TP18 TP19 TP22 TP23 U8 U9 U10 U11
component class BLDC: C60 C61 C62 C63 C64 C65 C66 C67 C68 C69 C70 C71 C72 C73 C74 C75 C76 C77 C78 C79 C80 C81 C82 C83 C84 C85 C86 C87 Q4 Q5 Q6 Q7 Q8 Q9 Q10 R50 R51 R52 R53 R54 R55 R56 R57 R58 R59 R60 R61 R62 R63 R64 R65 R66 R67 R68 R69 R70 R71 R72 R73 R74 R75 R76 R77 R78 R79 R80 R81 R82 R83 TP10 TP11 TP12 TP13 TP14 TP15 U5
component class Logo: Logo2
component class U_Hardware: FID1 FID2 FID3 LBL1 Logo1 Logo2 Logo3 Logo4 LOGO5 LOGO6 MP1 MP2 MP3 MP4
component class FiducialMark: FID1 FID2 FID3
component class Label: LBL1

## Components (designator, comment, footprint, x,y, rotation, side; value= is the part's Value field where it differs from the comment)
C1 "CGA2B2X8R1H102K050BA" 0402 101.681,11 r90 top value=1000pF
C2 "CGA2B2X8R1H102K050BA" 0402 101.731,14.303 r270 top value=1000pF
C3 "GCM155R71H104KE02D" 0402 138.071,49.998 r90 top value=0.1uF
C4 "GCM155R71H104KE02D" 0402 150.949,56.702 r90 top value=0.1uF
C5 "GRM32DC72A475KE01L" 1210_220 102.96,57.914 r90 top value=4.7uF
C6 "GRM32DC72A475KE01L" 1210_220 99.217,64.64 r0 top value=4.7uF
C7 "GCJ188L8EL104KA07D" 0603 106.353,71.658 r0 top value=0.1uF
C8 "EMVE101GTR331MMN0S" CAPSMT_62_MN0 141.6,69.2 r270 top value=330uF
C9 "GCJ188L8EL104KA07D" 0603 123.512,54.963 r180 bottom value=0.1uF
C10 "GCJ188L8EL104KA07D" 0603 108.859,74.515 r180 top value=0.1uF
C11 "GCM155R71H104KE02D" 0402 103.123,66.135 r180 top value=0.1uF
C12 "GCM31CR72A105KA03" 1206_180 102.422,61.741 r0 top value=1uF
C13 "CGA2B2X8R1H102K050BA" 0402 103.249,70.633 r180 top value=1000pF
C14 "CGA2B3X7S2A103K050BB" 0402 103.26,67.789 r180 top value=0.01uF
C15 "GCM155R71H104KE02D" 0402 108.842,60.404 r270 top value=0.1uF
C16 "GCM31CR72A105KA03" 1206_180 133.936,50.781 r0 top value=1uF
C17 "GCM155R71H104KE02D" 0402 108.842,60.404 r270 bottom value=0.1uF
C18 "CGA2B3X7S2A103K050BB" 0402 112.656,72.122 r0 top value=0.01uF
C19 "CGA2B3X7R1H683K050BB" 0402 112.947,66.535 r270 top value=0.068uF
C20 "GCM155R71H104KE02D" 0402 106.415,45.711 r0 top value=0.1uF
C21 "GRM32DC72A475KE01L" 1210_220 112.56,44.73 r270 top value=4.7uF
C22 "GRM32DC72A475KE01L" 1210_220 102.402,43.715 r270 top value=4.7uF
C23 "GCJ188L8EL104KA07D" 0603 102.523,43.622 r90 bottom value=0.1uF
C24 "GCJ188L8EL104KA07D" 0603 110.142,44.062 r90 top value=0.1uF
C25 "GRM32DC72A475KE01L" 1210_220 99.125,43.724 r270 top value=4.7uF
C26 "GCJ188L8EL104KA07D" 0603 98.811,48.55 r270 top value=0.1uF
C27 "GRM21BR61E226ME44L" 0805_HV 93.504,41.943 r270 top value=22uF
C28 "EMVE101GTR101MLH0S" CAPSMT_62_LH0 122.4,59.35 r0 top value=100uF
C29 "AGC0603X7R250-105KXP" FP-AGC0603X7R250-105KXP_0603-MFG 107.102,39.202 r90 top value=1µF
C30 "C0402C100K5RAC7867" FP-C0402C100K5RAC7867_0402-MFG 104.832,36.114 r180 top value=10pF
C31 "GRM21BR61E226ME44L" 0805_HV 92.167,49.005 r90 top value=22uF
C32 "GRM21BR61E226ME44L" 0805_HV 87.649,49.094 r90 top value=22uF
C33 "GRM21BR61E226ME44L" 0805_HV 89.884,49.043 r90 top value=22uF
C34 "GCM155R71H104KE02D" 0402 79.879,46.705 r180 bottom value=0.1uF
C35 "CGA2B2X8R1H102K050BA" 0402 79.879,47.896 r180 bottom value=1000pF
C36 "GCM155R71H104KE02D" 0402 79.902,49.156 r180 bottom value=0.1uF
C37 "GCM155R71H104KE02D" 0402 74.568,50.281 r180 bottom value=0.1uF
C38 "GCM155R71H104KE02D" 0402 84.058,45.191 r180 top value=0.1uF
C39 "GCM155R71H104KE02D" 0402 70.936,45.191 r180 top value=0.1uF
C40 "GRM21BR61E226ME44L" 0805_HV 62.49,48.513 r90 top value=22uF
C41 "CGA2B2X8R1H102K050BA" 0402 63.213,41.111 r180 top value=1000pF
C42 "GCM155R71H104KE02D" 0402 74.621,46.751 r0 bottom value=0.1uF
C43 "GCM155R71H104KE02D" 0402 65.075,49.158 r0 top value=0.1uF
C44 "GCM155R71H104KE02D" 0402 87.682,52.42 r180 bottom value=0.1uF
C45 "GCM155R71H104KE02D" 0402 88.569,55.41 r270 top value=0.1uF
C46 "GCM155R71H104KE02D" 0402 87.649,49.644 r180 bottom value=0.1uF
C47 "GCM155R71H104KE02D" 0402 69.25,56.216 r0 top value=0.1uF
C48 "GRM188Z71A106MA73D" 0603 65.075,50.801 r180 top value=10uF
C49 "GRM188Z71A106MA73D" 0603 87.903,50.973 r0 bottom value=10uF
C50 "GRM188Z71A106MA73D" 0603 87.164,55.618 r90 top value=10uF
C51 "GRM188Z71A106MA73D" 0603 87.849,48.165 r0 bottom value=10uF
C52 "GRM188Z71A106MA73D" 0603 69.135,54.818 r180 top value=10uF
C53 "GRM188R71A225KE15J" 0603 68.943,48.243 r0 bottom value=2.2uF
C54 "GRM188Z71A475ME15D" 0603 68.986,47.848 r0 top value=4.7uF
C55 "CGA2B2X8R1H102K050BA" 0402 96.704,28.621 r0 top value=1000pF
C56 "GRM21BR61E226ME44L" 0805_HV 63.577,42.967 r180 top value=22uF
C57 "GRM21BR61E226ME44L" 0805_HV 68.157,38.598 r90 top value=22uF
C58 "GCM155R71H104KE02D" 0402 69.935,38.084 r270 top value=0.1uF
C59 "CGA2B2X8R1H102K050BA" 0402 62.436,38.54 r0 top value=1000pF
C60 "EMVE101GTR331MMN0S" CAPSMT_62_MN0 86.7,69.538 r270 top value=330uF
C61 "GRM32DC72A475KE01L" 1210_220 36.457,73.654 r270 top value=4.7uF
C62 "RC0603FR-07200RL" 0603 45.369,36.218 r0 bottom value=10uF
C63 "AGC0603X7R250-105KXP" FP-AGC0603X7R250-105KXP_0603-MFG 44.494,35.343 r270 top value=1µF
C64 "AGC0603X7R250-105KXP" FP-AGC0603X7R250-105KXP_0603-MFG 46.293,35.253 r270 top value=1µF
C65 "AGC0603X7R250-105KXP" FP-AGC0603X7R250-105KXP_0603-MFG 41.443,35.37 r90 top value=1µF
C66 "CGA2B2X8R1H102K050BA" 0402 35.342,57.584 r270 top value=1000pF
C67 "AGC0603X7R250-105KXP" FP-AGC0603X7R250-105KXP_0603-MFG 39.233,36.143 r180 bottom value=1µF
C68 "GCM31CR72A105KA03" 1206_180 31.813,37.741 r90 top value=1uF
C69 "AGC0603X7R250-105KXP" FP-AGC0603X7R250-105KXP_0603-MFG 36.419,32.186 r180 bottom value=1µF
C70 "CGA2B2X8R1H102K050BA" 0402 35.935,59.839 r0 top value=1000pF
C71 "CGA2B2X8R1H102K050BA" 0402 35.327,54.925 r270 top value=1000pF
C72 "AGC0603X7R250-105KXP" FP-AGC0603X7R250-105KXP_0603-MFG 34.088,29.145 r180 bottom value=1µF
C73 "EMVE101GTR331MMN0S" CAPSMT_62_MN0 67.306,69.504 r270 top value=330uF
C74 "EMVE101GTR331MMN0S" CAPSMT_62_MN0 47.899,69.439 r270 top value=330uF
C75 "GRM32DC72A475KE01L" 1210_220 4.578,41.652 r0 top value=4.7uF
C76 "GRM32DC72A475KE01L" 1210_220 4.616,38.497 r0 top value=4.7uF
C77 "AGC0603X7R250-105KXP" FP-AGC0603X7R250-105KXP_0603-MFG 33.808,24.245 r180 bottom value=1µF
C78 "GRT155R71H471KE01D" 0402 85.702,8.595 r270 top value=470pF
C79 "GRT155R71H471KE01D" 0402 91.41,8.971 r270 top value=470pF
C80 "GRT155R71H471KE01D" 0402 90.175,8.952 r270 top value=470pF
C81 "CGA2B2X8R1H102K050BA" 0402 22.912,57.238 r270 top value=1000pF
C82 "CGA2B2X8R1H102K050BA" 0402 13.847,39.233 r270 top value=1000pF
C83 "GCM155R71H104KE02D" 0402 46.744,32.585 r180 bottom value=0.1uF
C84 "CGA2B2X8R1H102K050BA" 0402 23.66,59.119 r0 top value=1000pF
C85 "CGA2B2X8R1H102K050BA" 0402 23.596,55.31 r0 top value=1000pF
C86 "CGA2B2X8R1H102K050BA" 0402 14.414,41.157 r0 top value=1000pF
C87 "CGA2B2X8R1H102K050BA" 0402 13.847,36.642 r270 top value=1000pF
C88 "CGA2B2X8R1H102K050BA" 0402 96.608,17.8 r180 top value=1000pF
C89 "GCM155R71H104KE02D" 0402 124.937,36.444 r0 bottom value=0.1uF
C90 "CGA2B2X8R1H102K050BA" 0402 141.882,36.757 r0 top value=1000pF
C91 "GCM155R71H104KE02D" 0402 128.459,41.634 r180 bottom value=0.1uF
C92 "GCM155R71H104KE02D" 0402 128.459,40.393 r180 bottom value=0.1uF
C93 "GCM155R71H104KE02D" 0402 128.259,39.337 r180 top value=0.1uF
C94 "CGA2B2X8R1H102K050BA" 0402 141.883,38.076 r0 top value=1000pF
C95 "CGA3E3X7R1H334K080AB" 0603 123.616,41.749 r0 top value=0.33uF
C96 "GRM32DC72A475KE01L" 1210_220 47.541,7.545 r90 top value=4.7uF
C97 "GCJ188L8EL104KA07D" 0603 47.628,8.191 r270 bottom value=0.1uF
C98 "GCM155R71H104KE02D" 0402 55.373,11.205 r180 bottom value=0.1uF
C99 "GCM155R71H104KE02D" 0402 74.221,17.117 r0 bottom value=0.1uF
C100 "GCM155R71H104KE02D" 0402 82.703,8.595 r90 top value=0.1uF
C101 "GCM155R71H104KE02D" 0402 123.334,31.668 r0 bottom value=0.1uF
C102 "GCJ188L8EL104KA07D" 0603 128.859,29.664 r0 top value=0.1uF
C103 "GCM155R71H104KE02D" 0402 123.334,28.814 r0 bottom value=0.1uF
C104 "GCM188R72A472KA37D" 0603 138.418,32.794 r180 top value=4700pF
C105 "GCM155R71H104KE02D" 0402 125.689,46.29 r0 bottom value=0.1uF
C106 "GCJ188L8EL104KA07D" 0603 128.859,47.306 r180 bottom value=0.1uF
C107 "GCM155R71H104KE02D" 0402 125.702,44.892 r0 bottom value=0.1uF
C108 "GCM188R72A472KA37D" 0603 139.264,40.817 r0 top value=4700pF
C109 "GCM155R71H104KE02D" 0402 27.039,45.327 r0 top value=0.1uF
C110 "GCM155R71H104KE02D" 0402 88.565,8.895 r270 top value=0.1uF
C111 "GCM155R71H104KE02D" 0402 87.332,8.895 r270 top value=0.1uF
C112 "GCM155R71H104KE02D" 0402 27.07,50.246 r0 bottom value=0.1uF
C113 "GCM155R71H104KE02D" 0402 92.847,8.952 r270 top value=0.1uF
C114 "GCM155R71H104KE02D" 0402 84.456,8.649 r270 top value=0.1uF
C115 "CGA2B2X8R1H102K050BA" 0402 95.449,11.6 r270 top value=1000pF
C116 "GRM188Z71A475ME15D" 0603 85.843,16.789 r90 bottom value=4.7uF
C117 "GRM188Z71A475ME15D" 0603 88.189,18.723 r180 bottom value=4.7uF
C118 "CGA2B2X8R1H102K050BA" 0402 100.166,19.396 r180 top value=1000pF
C120 "CGA2B2X8R1H102K050BA" 0402 81.1,30.167 r90 top value=1000pF
C121 "GCM155R71H104KE02D" 0402 82.34,34.575 r180 top value=0.1uF
C122 "GCM155R71H104KE02D" 0402 105.002,21.031 r180 top value=0.1uF
C123 "GRM188Z71A106MA73D" 0603 85.302,27.387 r90 bottom value=10uF
C124 "GRM188Z71A106MA73D" 0603 77.052,21.117 r0 bottom value=10uF
C125 "GCM155R71H104KE02D" 0402 77.052,22.774 r0 bottom value=0.1uF
C126 "GCM155R71H104KE02D" 0402 81.788,16.43 r90 bottom value=0.1uF
C127 "GCM155R71H104KE02D" 0402 88.453,23.011 r180 bottom value=0.1uF
C128 "GCM155R71H104KE02D" 0402 88.479,25.342 r180 bottom value=0.1uF
C129 "GCM155R71H104KE02D" 0402 85.919,24.317 r270 bottom value=0.1uF
C130 "GCM155R71H104KE02D" 0402 83.062,24.23 r270 bottom value=0.1uF
C131 "GCM155R71H104KE02D" 0402 77.031,19.694 r0 bottom value=0.1uF
C132 "GCM155R71H104KE02D" 0402 78.012,14.341 r270 bottom value=0.1uF
C133 "GRM155R61E225ME15D" 0402 84.102,13.642 r180 bottom value=2.2uF
C134 "GRM155R61E225ME15D" 0402 88.432,16.838 r180 bottom value=2.2uF
C135 "GRM155R61E225ME15D" 0402 84.525,16.43 r90 bottom value=2.2uF
C136 "GRM155R61E225ME15D" 0402 88.264,20.317 r180 bottom value=2.2uF
C137 "GRM155R61E225ME15D" 0402 81.502,13.642 r0 bottom value=2.2uF
C138 "GRM155R61E225ME15D" 0402 80.562,27.767 r270 bottom value=2.2uF
C139 "GCM155R71H104KE02D" 0402 80.425,16.404 r90 bottom value=0.1uF
C140 "GCM155R71H104KE02D" 0402 83.108,16.43 r90 bottom value=0.1uF
C141 "GCM155R71H104KE02D" 0402 88.285,21.635 r180 bottom value=0.1uF
C142 "GCM155R71H104KE02D" 0402 88.485,24.191 r180 bottom value=0.1uF
C143 "GCM155R71H104KE02D" 0402 90.552,27.008 r0 bottom value=0.1uF
C144 "GCM155R71H104KE02D" 0402 78.84,26.752 r90 bottom value=0.1uF
C145 "GCM155R71H104KE02D" 0402 81.788,24.232 r270 bottom value=0.1uF
C146 "GCM155R71H104KE02D" 0402 84.448,24.23 r270 bottom value=0.1uF
C147 "GCM155R71H104KE02D" 0402 80.454,24.23 r270 bottom value=0.1uF
C148 "CGA2B2X8R1H102K050BA" 0402 96.663,20.67 r180 top value=1000pF
D1 "SMBJ51CA" SMB-Bi 154.229,77.4 r270 top value=51V
D2 "1N4148WS-7-F" SOD-323 105.271,64.098 r0 top value=75V
D3 "BAT46W-E3-08" SOD-123 124.092,50.999 r180 bottom value=100V
D4 "LTST-C191KGKT" LTST-C191_Green 92.453,39.202 r0 top value=Green
D5 "ESD2CAN24DBZRQ1" DBZ0003A-MFG 138.604,37.705 r0 top
D6 "1N4148WS-7-F" SOD-323 115.916,27.5 r0 top value=75V
D7 "1N4148WS-7-F" SOD-323 120.354,42.922 r0 top value=75V
D8 "LTST-C191TGKT" LTST-C191_Green 77.348,33.35 r270 top value=Green
D9 "LTST-C191KRKT" LTST-C191_Red 79.123,33.418 r270 top value=Red
D10 "MMSZ5265B-TP" FP-MMSZ5265B-TP_SOD123-MFG 105.764,60.712 r270 top
D11 "BZX84C27VDBZR" DBZ0003A-MFG 128.731,51.014 r180 bottom
D12 "BAT46W-E3-08" SOD-123 81.302,6.255 r0 top value=100V
D13 "MMSZ5240BS-7-F" SOD-323 94.589,45.549 r270 bottom value=10V
FID1 "Fiducial" Fiducial10-20 21.629,32.617 r0 top
FID2 "Fiducial" Fiducial10-20 63.036,54.535 r0 top
FID3 "Fiducial" Fiducial10-20 118.69,22.706 r0 top
J1 "CON" Pin_1.7x1.1mm 145.7,44 r90 top locked
J2 "CON" Pin_1.7x1.1mm 145.7,38.3 r90 top locked
J3 "CON" Pin_3.3x1.3mm 154.1,65.2 r90 top locked
J4 "CON" Pin_3.3x1.3mm 154.1,51.539 r90 top locked
J5 "CON" Pin_1.9x0.9mm 55.834,4.1 r180 top
J6 "CON" Pin_1.9x0.9mm 50.859,3.504 r0 top
J7 "CON" Pin_3.3x1.4mm 27.05,67.498 r0 top locked
J8 "CON" Pin_3.3x1.4mm 13.102,61.651 r45 top locked
J9 "CON" Pin_3.3x1.4mm 7.28,47.793 r270 top locked
J10 "61000418221" Wurth_61000418221 73.149,31.645 r0 top
J11 "CON" Pin_1.7x1.1mm 141.3,50.999 r90 top
J12 "CON" Pin_1.7x1.1mm 141.2,44.4 r90 top
J13 "CON" Pin_1.7x1.1mm 141.3,47.9 r270 top
J14 "CON" Pin_1.7x1.1mm 149.1,44 r270 top locked
J15 "CON" Pin_3.3x1.3mm 154.1,58.291 r90 top locked
J16 "CON" Pin_1.7x1.1mm 149.1,38.3 r90 top locked
J17 "CON" Pin_1.7x1.1mm 149.1,34.311 r90 top locked
J18 "CON" Pin_1.7x1.1mm 145.7,34.311 r90 top locked
J19 "CON" Pin_1.7x1.1mm 149.1,48.05 r90 top locked
J20 "CON" Pin_1.7x1.1mm 145.65,48.05 r90 top locked
J21 "61000418221" Wurth_61000418221 28.74,41.543 r270 top
J22 "61000418221" Wurth_61000418221 44.002,47.463 r270 top
J23 "61000418221" Wurth_61000418221 104.194,26.95 r180 top
L1 "744309025" WE-HCM_1390 124.189,75.002 r180 top value=250nH
L2 "74437349033" WE-LHMI_7050 104.249,50.085 r180 top value=3.3uH
L3 "74438334022" WE-MAPI_3012 77.074,41.32 r0 top value=2.2uH
L4 "XGL4030-102MEC" FP-XGL4030-102MEC_SMD_IND_4MM0_4MM0-MFG 66.361,34.394 r0 top value=1uH
L5 "ACT45B-101-2P-TL003" ACT45B 132.951,32.615 r180 top value=100uH
L6 "ACT45B-101-2P-TL003" ACT45B 134.051,45.468 r90 top value=100uH
L7 "742792731" 0402 88.389,15.681 r180 bottom value="100 ohm"
L8 "742792731" 0402 91.003,17.873 r90 bottom value="100 ohm"
L10 "742792731" 0402 88.677,14.465 r0 bottom value="100 ohm"
LBL1 "THT-14-423-10" Label_650x200 67.404,4.56 r0 top
Logo1 "CE Mark" CE_Mark_5mm 54.383,54.126 r0 top
Logo2 "Texas Instruments" TI_Stacked_Overlay_Small 57.941,20.999 r0 top
Logo3 "FCC disclaimer" FCC_disclaimer 62.954,-2 r0 top
Logo4 "WEEE logo" WEEE_Minimum 50.973,41.192 r0 top
LOGO5 "CAUTION HOT SURFACE" IEC_HotSurface_Small 5.423,64.359 r0 top
LOGO6 "DANGER HIGH VOLTAGE" IEC_HighVoltage_Small 154.7,70.892 r0 top
MP1 "29344" FP-29344_SCREW-MFG 36.843,17.837 r0 top
MP2 "29344" FP-29344_SCREW-MFG 114.852,17.931 r0 top
MP3 "29344" FP-29344_SCREW-MFG 113.121,76.482 r0 top
MP4 "29344" FP-29344_SCREW-MFG 55,48 r0 top
Q1 "SQJA90EP-T1_GE3" PowerPAK_SO-8L 106.554,78.041 r0 top value=80V
Q2 "SQJA90EP-T1_GE3" PowerPAK_SO-8L 99.646,78.041 r180 top value=80V
Q3 "DMN3053L-7" SOT-23 95.899,45.341 r0 top value=30V
Q4 "SQJA90EP-T1_GE3" PowerPAK_SO-8L 31.457,74.078 r90 top value=80V
Q5 "SQJA90EP-T1_GE3" PowerPAK_SO-8L 34.187,65.582 r90 top value=80V
Q6 "BCR22PNH6327XTSA1" FP-BCR22PNH6327XTSA1_SOT363-MFG 40.375,40.216 r180 top value=50V
Q7 "SQJA90EP-T1_GE3" PowerPAK_SO-8L 12.503,68.858 r180 top value=80V
Q8 "SQJA90EP-T1_GE3" PowerPAK_SO-8L 6.706,55.047 r180 top value=80V
Q9 "SQJA90EP-T1_GE3" PowerPAK_SO-8L 20.204,64.518 r90 top value=80V
Q10 "SQJA90EP-T1_GE3" PowerPAK_SO-8L 13.381,47.031 r90 top value=80V
Q11 "SQJA90EP-T1_GE3" PowerPAK_SO-8L 42.358,8.83 r180 top value=80V
Q12 "ZXMN10A07FTA" SOT-23 96.275,49.998 r270 top value=100V
R1 "CRCW0402100KFKED" 0402 103.057,11 r270 top value=100k
R2 "CRCW0402100KFKED" 0402 102.966,14.303 r90 top value=100k
R3 "CRCW040269K8FKED" 0402 104.342,11 r90 top value=69.8k
R4 "CRCW040269K8FKED" 0402 104.256,14.335 r90 top value=69.8k
R5 "CRCW040210K0FKED" 0402 138.715,45.54 r270 top value=10.0k
R6 "CRCW040210K0FKED" 0402 152.4,44 r0 top value=10.0k
R7 "BVN-M-R001-1.0" FP-BVN-M-R001-1.0_1612-MFG 98.776,71.465 r90 top value=1m
R8 "CRCW04020000Z0ED" 0402 101.853,81.421 r0 top value=0
R9 "CRCW04020000Z0ED" 0402 104.51,74.515 r180 top value=0
R10 "CRCW04021K00FKED" 0402 103.249,71.845 r180 top value=1.00k
R11 "504L50R0FTNCFT" 0402 103.249,69.039 r180 top value=50
R12 "CRCW0402100KFKED" 0402 107.48,63.136 r90 top value=100k
R13 "CRCW0402100KFKED" 0402 108.886,63.041 r90 bottom value=100k
R14 "CRCW04021K74FKED" 0402 107.48,60.404 r90 top value=1.74k
R15 "CRCW040210K0FKED" 0402 83.546,35.77 r180 top value=10.0k
R16 "CRCW0402100RFKED" 0402 109.996,72.122 r180 top value=100
R17 "CRCW04021K00FKED" 0402 110.74,63.775 r180 bottom value=1.00k
R18 "CRCW04027K50FKED" 0402 113.735,68.589 r180 top value=7.50k
R19 "CRCW04021K00FKED" 0402 110.919,63.912 r90 top value=1.00k
R20 "CRCW040226K1FKED" 0402 113.171,69.877 r180 top value=26.1k
R21 "CRCW0402100KFKED" 0402 111.771,66.539 r90 top value=100k
R22 "CRCW04020000Z0ED" 0402 99.478,43.601 r0 bottom value=0
R23 "CRCW04020000Z0ED" 0402 95.9,42.73 r0 top value=0
R24 "CRCW04021K00FKED" 0402 91.665,41.917 r90 top value=1.00k
R25 "CRCW04020000Z0ED" 0402 102.802,39.207 r270 top value=0
R26 "CRCW04021K00FKED" 0402 110.061,41.634 r180 top value=1.00k
R27 "CRCW0402100KFKED" 0402 99.9,45.555 r90 bottom value=100k
R28 "CRCW04021K00FKED" 0402 95.676,47.591 r0 top value=1.00k
R29 "CRCW04020000Z0ED" 0402 109.842,39.259 r90 top value=0
R30 "CRCW04020000Z0ED" 0402 108.598,39.259 r270 top value=0
R31 "CRCW0402100KFKED" 0402 100.933,36.505 r0 bottom value=100k
R32 "CRCW0402100KFKED" 0402 104.787,38.572 r0 top value=100k
R33 "CRCW0402100KFKED" 0402 104.777,37.316 r0 top value=100k
R34 "CRCW04027K15FKED" 0402 104.777,39.807 r0 top value=7.15k
R35 "CRCW04027K15FKED" 0402 107.358,37.316 r180 top value=7.15k
R36 "CRCW04021K00FKED" 0402 84.109,46.441 r180 top value=1.00k
R37 "CRCW04020000Z0ED" 0402 69.072,49.363 r0 top value=0
R38 "CRCW04020000Z0ED" 0402 84.146,49.005 r180 top value=0
R39 "CRCW04020000Z0ED" 0402 84.193,50.935 r180 top value=0
R40 "CRCW04020000Z0ED" 0402 84.292,54.818 r180 top value=0
R41 "CRCW04020000Z0ED" 0402 70.617,53.485 r0 top value=0
R42 "CRCW040233R0JNED" 0402 70.712,51.24 r0 top value=33
R43 "CRCW0402100RFKED" 0402 96.069,30.793 r270 top value=100
R44 "CRCW040216K2FKED" 0402 69.935,40.663 r270 top value=16.2k
R45 "CRCW04020000Z0ED" 0402 66.439,42.236 r90 top value=0
R46 "CRCW0402107KFKED" 0402 63.077,35.359 r270 top value=107k
R47 "CRCW040215K0FKED" 0402 67.638,42.261 r90 top value=15.0k
R48 "CRCW0402100KFKED" 0402 62.442,37.294 r180 top value=100k
R49 "CRCW04020000Z0ED" 0402 62.436,39.817 r0 top value=0
R50 "CRCW04020000Z0ED" 0402 36.956,70.011 r0 top value=0
R51 "CRCW04020000Z0ED" 0402 87.452,43.706 r0 top value=0
R52 "CRCW0402100KFKED" 0402 34.33,70.011 r0 top value=100k
R53 "CRCW04020000Z0ED" 0402 44.494,39.938 r270 top value=0
R54 "CRCW04020000Z0ED" 0402 48.542,34.528 r180 top value=0
R55 "CRCW04020000Z0ED" 0402 38.299,58.284 r270 top value=0
R56 "CRCW0402100KFKED" 0402 37.441,62.027 r90 top value=100k
R57 "CRCW04020000Z0ED" 0402 42.34,40.266 r270 top value=0
R58 "CRCW04020000Z0ED" 0402 39.212,37.959 r180 bottom value=0
R59 "CRCW040233R0JNED" 0402 53.035,26.855 r180 top value=33
R60 "CRCW040210R0FKED" 0402 34.049,59.102 r270 top value=10.0
R61 "BVN-Z-R0005-1.0" FP-BVN-Z-R0005-1.0_1612-MFG 31.138,58.002 r90 top value=500µ
R62 "CRCW040210K0FKED" 0402 49.004,30.682 r0 bottom value=10.0k
R63 "CRCW040210R0FKED" 0402 34.035,56.478 r90 top value=10.0
R64 "KTR03EZPF3R00" 0603 36.419,33.839 r180 bottom value=3.00
R65 "KTR03EZPF3R00" 0603 34.152,27.427 r180 bottom value=3.00
R66 "CRCW04020000Z0ED" 0402 18.397,71.338 r0 top value=0
R67 "CRCW04020000Z0ED" 0402 12.8,56.594 r0 top value=0
R68 "KTR03EZPF3R00" 0603 34.138,25.765 r180 bottom value=3.00
R69 "CRCW0402100KFKED" 0402 16.566,70.717 r90 top value=100k
R70 "CRCW0402100KFKED" 0402 10.7,56.4 r90 top value=100k
R71 "CRCW0402162RFKED" 0402 85.843,5.702 r270 top value=162
R72 "CRCW04020000Z0ED" 0402 24.942,61.781 r270 top value=0
R73 "CRCW04020000Z0ED" 0402 17.939,44.169 r270 top value=0
R74 "CRCW0402100KFKED" 0402 23.433,61.78 r90 top value=100k
R75 "CRCW0402100KFKED" 0402 16.566,44.208 r90 top value=100k
R76 "CRCW0402162RFKED" 0402 91.445,5.791 r270 top value=162
R77 "CRCW0402162RFKED" 0402 90.175,5.791 r270 top value=162
R78 "CRCW040210R0FKED" 0402 21.66,58.438 r270 top value=10.0
R79 "CRCW040210R0FKED" 0402 12.522,40.557 r270 top value=10.0
R80 "BVN-Z-R0005-1.0" FP-BVN-Z-R0005-1.0_1612-MFG 18.92,57.035 r90 top value=500µ
R81 "BVN-Z-R0005-1.0" FP-BVN-Z-R0005-1.0_1612-MFG 9.47,39.31 r90 top value=500µ
R82 "CRCW040210R0FKED" 0402 21.629,55.798 r90 top value=10.0
R83 "CRCW040210R0FKED" 0402 12.534,37.937 r90 top value=10.0
R84 "CRCW0402100RFKED" 0402 102.627,17.963 r180 top value=100
R85 "CRCW040210R0FKED" 0402 45.418,13.122 r180 top value=10.0
R86 "CRCW040210R0FKED" 0402 128.259,36.787 r0 top value=10.0
R87 "CRCW0402100KFKED" 0402 45.426,11.849 r180 top value=100k
R88 "CRCW040210R0FKED" 0402 128.259,38.105 r0 top value=10.0
R89 "CRCW040233R0JNED" 0402 120.316,39.433 r0 top value=33
R90 "CRCW040210R0FKED" 0402 73.919,8.754 r270 top value=10.0
R91 "CRCW040210K0FKED" 0402 49.069,10.425 r180 top value=10.0k
R92 "CRCW040210K0FKED" 0402 49.069,13.005 r0 top value=10.0k
R93 "CRCW040233R0JNED" 0402 60.982,10.092 r180 top value=33
R94 "CRCW040233R0JNED" 0402 58.32,10.947 r180 top value=33
R95 "CRCW04021K00FKED" 0402 49.069,11.694 r0 top value=1.00k
R96 "CRCW040233R0JNED" 0402 53.96,15.141 r180 top value=33
R97 "CRCW04020000Z0ED" 0402 126.136,34.982 r180 bottom value=0
R98 "CRCW04020000Z0ED" 0402 132.951,35.17 r180 top value=0
R99 "CRCW04020000Z0ED" 0402 130.383,48.501 r0 bottom value=0
R100 "CRCW040260R4FKED" 0402 137.347,34.18 r180 top value=60.4
R101 "CRCW040233R0JNED" 0402 118.993,34.029 r0 top value=33
R102 "CRCW040210K0FKED" 0402 118.993,27.5 r180 top value=10.0k
R103 "CRCW040260R4FKED" 0402 137.376,31.565 r0 top value=60.4
R104 "CRCW040210K0FKED" 0402 127.356,27.439 r270 top value=10.0k
R105 "CRCW04020000Z0ED" 0402 132.951,29.997 r180 top value=0
R106 "CRCW040233R0JNED" 0402 125.637,33.508 r0 top value=33
R107 "CRCW040233R0JNED" 0402 118.993,28.908 r0 top value=33
R108 "CRCW040233R0JNED" 0402 118.993,30.264 r0 top value=33
R109 "CRCW04020000Z0ED" 0402 136.492,45.44 r90 top value=0
R110 "CRCW040260R4FKED" 0402 142.218,41.634 r0 top value=60.4
R111 "CRCW040233R0JNED" 0402 121.454,47.591 r0 top value=33
R112 "CRCW040210K0FKED" 0402 123.403,43.127 r180 top value=10.0k
R113 "CRCW040260R4FKED" 0402 142.225,40.436 r180 top value=60.4
R114 "CRCW040210K0FKED" 0402 129.519,42.941 r0 top value=10.0k
R115 "CRCW04020000Z0ED" 0402 131.455,45.492 r90 top value=0
R116 "CRCW040233R0JNED" 0402 126.702,49.501 r0 top value=33
R117 "CRCW040233R0JNED" 0402 121.536,44.637 r0 top value=33
R118 "CRCW040233R0JNED" 0402 121.473,46.264 r0 top value=33
R119 "CRCW04021K00FKED" 0402 88.74,5.8 r90 top value=1.00k
R120 "CRCW0402100KFKED" 0402 29.7,50.229 r0 top value=100k
R121 "CRCW04021K00FKED" 0402 87.457,5.8 r90 top value=1.00k
R122 "CRCW0402100KFKED" 0402 27.071,50.246 r180 top value=100k
R123 "CRCW04021K00FKED" 0402 92.847,5.702 r90 top value=1.00k
R124 "CRCW0402100KFKED" 0402 29.7,45.327 r0 bottom value=100k
R125 "CRCW04021K00FKED" 0402 84.456,5.745 r90 top value=1.00k
R126 "CRCW0402100KFKED" 0402 27.015,45.293 r180 bottom value=100k
R127 "CRCW040226K1FKED" 0402 99.798,38.759 r90 top value=26.1k
R128 "CRCW04020000Z0ED" 0402 96.608,14.163 r0 top value=0
R129 "CRCW04020000Z0ED" 0402 96.608,15.367 r0 top value=0
R130 "CRCW040210K0FKED" 0402 99.603,32.987 r270 top value=10.0k
R131 "CRCW04021K00FKED" 0402 96.695,19.501 r180 top value=1.00k
R132 "CRCW04021K00FKED" 0402 96.739,11.6 r90 top value=1.00k
R133 "CRCW040233R0JNED" 0402 96.715,23.452 r180 top value=33
R134 "CRCW04021K00FKED" 0402 91.144,30.197 r270 top value=1.00k
R135 "CRCW040233R0JNED" 0402 96.75,24.782 r180 top value=33
R136 "CRCW040210K0FKED" 0402 92.357,30.197 r270 top value=10.0k
R137 "CRCW040233R0JNED" 0402 82.316,30.158 r270 top value=33
R138 "CRCW0402100RFKED" 0402 96.75,27.039 r0 top value=100
R139 "CRCW0402100RFKED" 0402 100.179,28.513 r0 top value=100
R140 "CRCW040233R0JNED" 0402 89.827,30.197 r90 top value=33
R141 "CRCW040233R0JNED" 0402 71.149,17.094 r0 top value=33
R142 "CRCW040233R0JNED" 0402 87.882,30.197 r90 top value=33
R143 "CRCW040233R0JNED" 0402 71.149,13.958 r0 top value=33
R144 "CRCW04020000Z0ED" 0402 79.11,8.654 r270 top value=0
R145 "CRCW04020000Z0ED" 0402 80.902,8.695 r270 top value=0
R146 "CRCW04020000Z0ED" 0402 83.771,30.202 r90 top value=0
R147 "CRCW040210K0FKED" 0402 69.031,26.562 r90 top value=10.0k
R148 "CRCW040210K0FKED" 0402 70.695,24.482 r0 top value=10.0k
R149 "CRCW040210K0FKED" 0402 70.336,26.553 r90 top value=10.0k
R150 "CRCW040210K0FKED" 0402 73.669,24.482 r0 top value=10.0k
R151 "CRCW04021K00FKED" 0402 77.631,30.173 r270 top value=1.00k
R152 "CRCW04021K00FKED" 0402 79.123,30.193 r270 top value=1.00k
R153 "CRCW040210K0FKED" 0402 108.013,74.059 r270 bottom value=10.0k
R154 "CRCW04021K00FKED" 0402 88.703,39.955 r180 top value=1.00k
R155 "CRCW0402100KFKED" 0402 96.311,52.531 r180 top value=100k
R156 "CRCW040210K0FKED" 0402 110.362,21.96 r270 top value=10.0k
TP1 "5015" Testpoint_Keystone_Miniature 76.906,80.518 r90 top
TP2 "5015" Testpoint_Keystone_Miniature 42.68,16.325 r0 top
TP3 "5015" Testpoint_Keystone_Miniature 92.004,45.617 r0 top
TP4 "5015" Testpoint_Keystone_Miniature 63.989,45.349 r180 top
TP5 "5015" Testpoint_Keystone_Miniature 57.35,41.798 r0 top
TP6 "5015" Testpoint_Keystone_Miniature 119.575,32.158 r180 top
TP7 "5015" Testpoint_Keystone_Miniature 88.062,52.685 r0 top
TP8 "5015" Testpoint_Keystone_Miniature 145.286,52.431 r0 top
TP9 "5015" Testpoint_Keystone_Miniature 150.028,52.364 r0 top
TP10 "5015" Testpoint_Keystone_Miniature 42.847,52.26 r180 top
TP11 "5015" Testpoint_Keystone_Miniature 42.843,55.31 r180 top
TP12 "5015" Testpoint_Keystone_Miniature 33.288,27.765 r180 top
TP13 "5015" Testpoint_Keystone_Miniature 29.137,24.965 r0 top
TP14 "5015" Testpoint_Keystone_Miniature 28.996,29.384 r0 top
TP15 "5015" Testpoint_Keystone_Miniature 33.288,22.1 r180 top
TP16 "5015" Testpoint_Keystone_Miniature 113.617,39.109 r0 top
TP17 "5015" Testpoint_Keystone_Miniature 113.269,33.129 r0 top
TP18 "5015" Testpoint_Keystone_Miniature 117.606,48.112 r180 top
TP19 "5015" Testpoint_Keystone_Miniature 112.697,24.765 r0 top
TP22 "5015" Testpoint_Keystone_Miniature 111.582,30.264 r0 top
TP23 "5015" Testpoint_Keystone_Miniature 116.995,44.895 r180 top
U1 "LM74930QRGEQ1" RGE0024T-MFG 108.336,67.789 r90 top
U2 "LM68645SCRZTRQ1" RZT0020A-MFG 106.502,43.381 r90 top
U3 "O386005QDCARQ1" DCA0048J-MFG 77.074,49.735 r180 top
U4 "TPS62902QRYTRQ1" RYT0009A-MFG 65.536,38.365 r90 top
U5 "DRV3263AERGZRQ1" RGZ0048N-MFG 42.743,28.515 r90 top
U6 "WSS001DDRRRQ1" DRR0012E-MFG 124.181,39.009 r180 top
U7 "DRV8263SQVAKRQ1" VAK0015A-MFG 53.71,9.295 r0 top
U8 "TCAN1043HGDMTRQ1" DMT0014A 124.736,30.308 r0 top
U9 "ESD2CAN48DBZRQ1" DBZ0003A-MFG 141.883,32.987 r180 top
U10 "TCAN1043HGDMTRQ1" DMT0014A 126.489,46.29 r0 top
U11 "ESD2CAN48DBZRQ1" DBZ0003A-MFG 135.792,40.817 r0 top
U12 "TMAG6180EDGKRQ1" DGK0008A-MFG 27,47.75 r180 top
U13 "TMAG6180EDGKRQ1" DGK0008A-MFG 26.989,47.752 r180 bottom
U14 "F29P329SM2QPZSQ1" PZS0100A-MFG 84.502,20.317 r90 top locked
Y1 "CDC6C025000ADLYRQ1" DLY0004D-MFG 82.002,32.814 r0 top

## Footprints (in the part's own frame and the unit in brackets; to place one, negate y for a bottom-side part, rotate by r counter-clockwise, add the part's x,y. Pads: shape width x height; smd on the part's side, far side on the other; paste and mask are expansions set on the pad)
0402 [mm] "0402 from SM-752 data"
  rect 0.8x0.6 smd: 1(-0.6,0) 2(0.6,0)
  silkscreen extent -1.22,-0.52 1.22,0.52, body extent -0.55,-0.3 0.55,0.3, height 0.6
0603 [mm] "0603 from SM-752 data"
  rect 1x0.95 smd: 1(-0.8,0) 2(0.8,0)
  silkscreen extent -1.52,-0.69 1.52,0.69, body extent -0.87,-0.47 0.87,0.47, height 1
0805_HV [mil] "0805 with 30mil clearance between pads"
  rect 50x63 smd: 1(-40,0) 2(40,0)
  silkscreen extent -74,-40 74,40, body extent -43,-29 43,29, height 57
1206_180 [mm] "1206_180"
  rect 1.1x1.6 smd: 1(-1.7,0) 2(1.7,0)
  silkscreen extent -0.9,-1 0.9,1, body extent -1.75,-0.95 1.75,0.95, height 1.8
1210_220 [mm] "1210"
  rect 1.3x2.7 smd: 1(-1.45,0) 2(1.45,0)
  silkscreen extent -2.32,-1.57 2.32,1.57, body extent -1.7,-1.35 1.7,1.35, height 2.2
ACT45B [mm] "SMD, 4-Leads, Body 4.7 x 3.7 mm"
  rect 1.35x0.9 smd: 1(-2.275,1.25) 2(-2.275,-1.25) 3(2.275,-1.25) 4(2.275,1.25)
  silkscreen extent -2.35,-1.7 2.35,2, body extent -2.35,-1.7 2.35,1.7, height 3
CAPSMT_62_LH0 [mm] "16 x 16.5mm:  Chemi-Con LH0"
  rect 7.8x9.6 smd: 1(-6.25,0) 2(6.25,0)
  silkscreen extent -8.55,-8.55 8.55,8.55, body extent -8.55,-8.55 8.55,8.55, height 17
CAPSMT_62_MN0 [mm] "18 x 21.5mm:  Chemi-Con MN0"
  rect 8.8x9.6 smd: 1(-6.75,0) 2(6.75,0)
  silkscreen extent -9.6,-9.6 9.6,9.6, body extent -9.6,-9.6 9.6,9.6, height 22
CE_Mark_5mm [mm] "Minimum text height for CE Mark"
  silkscreen extent -3.5,-2.5 3.5,2.5
DBZ0003A-MFG [mm] "Recommended Land Pattern"
  rrect17% 1.3x0.6 smd paste+0 mask+0: 1(-1.05,0.95) 2(-1.05,-0.95) 3(1.05,0)
  silkscreen extent -0.7,-1.52 0.7,1.52, body extent -1.18,-1.46 1.18,1.46, height 1.12
DCA0048J-MFG [mm]
  rrect33% 1.5x0.3 smd paste+0 mask+0: 1(-3.75,5.75) 2(-3.75,5.25) 3(-3.75,4.75) 4(-3.75,4.25) 5(-3.75,3.75) 6(-3.75,3.25) 7(-3.75,2.75) 8(-3.75,2.25) 9(-3.75,1.75) 10(-3.75,1.25) 11(-3.75,0.75) 12(-3.75,0.25) 13(-3.75,-0.25) 14(-3.75,-0.75) 15(-3.75,-1.25) 16(-3.75,-1.75) 17(-3.75,-2.25) 18(-3.75,-2.75) 19(-3.75,-3.25) 20(-3.75,-3.75) 21(-3.75,-4.25) 22(-3.75,-4.75) 23(-3.75,-5.25) 24(-3.75,-5.75) 25(3.75,-5.75) 26(3.75,-5.25) 27(3.75,-4.75) 28(3.75,-4.25) 29(3.75,-3.75) 30(3.75,-3.25) 31(3.75,-2.75) 32(3.75,-2.25) 33(3.75,-1.75) 34(3.75,-1.25) 35(3.75,-0.75) 36(3.75,-0.25) 37(3.75,0.25) 38(3.75,0.75) 39(3.75,1.25) 40(3.75,1.75) 41(3.75,2.25) 42(3.75,2.75) 43(3.75,3.25) 44(3.75,3.75) 45(3.75,4.25) 46(3.75,4.75) 47(3.75,5.25) 48(3.75,5.75)
  silkscreen extent -5.2,-6.3 3.1,6.3, body extent -4.6,-6.55 4.6,6.55, height 0.25
DGK0008A-MFG [mm]
  rrect22% 1.45x0.45 smd paste+0 mask+0: 1(-2.2,0.975) 2(-2.2,0.325) 3(-2.2,-0.325) 4(-2.2,-0.975) 5(2.2,-0.975) 6(2.2,-0.325) 7(2.2,0.325) 8(2.2,0.975)
  silkscreen extent -3.61,-1.55 1.1,1.55, body extent -3.03,-1.8 3.03,1.8, height 0.25
DLY0004D-MFG [mm] "Recommended Land Pattern"
  rrect29% 0.6x0.35 smd paste+0 mask+0: 1(-0.5,0.525) 2(-0.5,-0.525) 3(0.5,-0.525) 4(0.5,0.525)
  silkscreen extent -1.47,-1.07 0.65,1.07, body extent -0.6,-0.8 0.6,0.8, height 1
DMT0014A [mm] "SON, 14-Leads, Body 3x4.5mm, Pitch 0.65mm"
  rrect33% 0.6x0.3 smd: 1(-1.4,1.95) 2(-1.4,1.3) 3(-1.4,0.65) 4(-1.4,0) 5(-1.4,-0.65) 6(-1.4,-1.3) 7(-1.4,-1.95) 8(1.4,-1.95) 9(1.4,-1.3) 10(1.4,-0.65) 11(1.4,0) 12(1.4,0.65) 13(1.4,1.3) 14(1.4,1.95)
  rrect6% 1.6x4.2 smd paste-1.6: 15(0,0)
  rrect8% 1.47x1.18 on Top Paste: ""(0,-1.4) ""(0,-0.02) ""(0,1.36)
  silkscreen extent -2.1,-2.54 2.1,2.5, body extent -1.5,-2.25 1.5,2.25, height 0.91
DRR0012E-MFG [mm]
  rrect40% 0.62x0.25 smd paste+0 mask+0: 1(-1.39,1.25) 2(-1.39,0.75) 3(-1.39,0.25) 4(-1.39,-0.25) 5(-1.39,-0.75) 6(-1.39,-1.25) 7(1.39,-1.25) 8(1.39,-0.75) 9(1.39,-0.25) 10(1.39,0.25) 11(1.39,0.75) 12(1.39,1.25)
  rrect8% 1.3x2.5 smd paste-1000 mask+0: 13(0,0)
  silkscreen extent -2.38,-1.75 1.55,1.75, body extent -1.8,-1.65 1.8,1.65, height 0.25
FCC_disclaimer [mm]
Fiducial10-20 [mm]
  round 1 smd mask+0.5: 1(0,0)
  Top Layer keep-out circle w1.178: c0,0 r0.5
FP-29344_SCREW-MFG [mm] "Recommended Land Pattern"
  round 3.15 hole 3.15 unplated paste-2539.97 mask+0: ""(0,0)
  silkscreen extent -2.82,-2.82 2.83,2.82, body extent -2.7,-2.69 2.7,2.69, height 1.95
FP-AGC0603X7R250-105KXP_0603-MFG [mm] "Recommended Land Pattern"
  rrect10% 1x1 smd paste+0 mask+0: 1(-0.8,0) 2(0.8,0)
  silkscreen extent -0.87,-0.87 0.87,0.87, body extent -0.8,-0.4 0.8,0.4, height 0.95
FP-BCR22PNH6327XTSA1_SOT363-MFG [mm]
  rrect33% 0.7x0.3 smd paste+0 mask+0: 1(-0.8,0.65) 2(-0.8,0) 3(-0.8,-0.65) 4(0.8,-0.65) 5(0.8,0) 6(0.8,0.65)
  silkscreen extent -1.85,-1.1 0.08,1.1, body extent -1.25,-1.2 1.25,1.2, height 0.25
FP-BVN-M-R001-1.0_1612-MFG [mm]
  rrect7% 1.5x2.95 smd paste+0 mask+0: 1(-1.05,0.6) 2(1.05,0.6)
  rrect14% 1.5x0.7 smd paste+0 mask+0: 3(-1.05,-1.725) 4(1.05,-1.725)
  silkscreen extent -2.47,-2.45 1.55,2.45, body extent -1.9,-2.17 1.9,2.17, height 0.25
FP-BVN-Z-R0005-1.0_1612-MFG [mm] "Recommended Land Pattern"
  rrect7% 1.5x2.95 smd paste+0 mask+0: 1(-1.05,0.6) 2(1.05,0.6)
  rrect14% 1.5x0.7 smd paste+0 mask+0: 3(-1.05,-1.725) 4(1.05,-1.725)
  silkscreen extent -2.47,-2.45 1.55,2.45, body extent -1.55,-2 1.55,2.1, height 1.9
FP-C0402C100K5RAC7867_0402-MFG [mm]
  rrect19% 0.52x0.52 smd paste+0 mask+0: 1(-0.4,0) 2(0.4,0)
  silkscreen extent -0.5,-0.64 0.5,0.64, body extent -0.8,-0.4 0.8,0.4, height 0.25
FP-MMSZ5265B-TP_SOD123-MFG [mm] "Recommended Land Pattern"
  rrect11% 0.91x1.22 smd paste+0 mask+0: 1(-1.635,0) 2(1.635,0)
  silkscreen extent -2.77,-0.9 0.8,0.9, body extent -1.85,-0.8 1.85,0.8, height 1.35
FP-XGL4030-102MEC_SMD_IND_4MM0_4MM0-MFG [mm]
  rrect10% 0.98x3.4 smd paste+0 mask+0: 1(-1.185,0) 2(1.185,0)
  silkscreen extent -2.15,-2.15 2.15,2.15, body extent -2.25,-2.25 2.25,2.25, height 0.25
IEC_HighVoltage_Small [mm]
  silkscreen extent -2.72,-2.24 2.72,2.47
IEC_HotSurface_Small [mm]
  silkscreen extent -2.72,-2.36 2.72,2.35
Label_650x200 [mil] "Thermal Transfer Label"
  round 1 on Mech13: 0(0,0)
  silkscreen extent -325,-100 325,100, body extent -325,-100 325,100, height 1
LTST-C191_Green [mm] "Lite-On"
  rect 0.8x0.8 smd: 1(-0.75,0) 2(0.75,0)
  silkscreen extent -1.1,-0.8 1.8,0.8, body extent -0.85,-0.45 0.85,0.45, height 0.65
LTST-C191_Red [mm] "SMD, 2-Leads, Body1.6x0.8mm"
  rect 0.8x0.8 smd: 1(-0.75,0) 2(0.75,0)
  silkscreen extent -1.2,-0.8 1.85,0.8, body extent -0.85,-0.45 0.85,0.45, height 0.66
Pin_1.7x1.1mm [mm] "single pin connector1.7*1.1mm"
  rect 2.2x1.6 hole 1.1 slot 1.7 at 0 deg: 1(0,0)
Pin_1.9x0.9mm [mm] "single pin connector 1.9*0.9mm"
  rect 2.3x1.7 hole 1.2 slot 1.8 at 0 deg: 1(0,0)
Pin_3.3x1.3mm [mm] "single pin connector 3.3x1.3mm"
  rect 4.3x2.3 hole 1.3 slot 3.3 at 0 deg: 1(0,0)
Pin_3.3x1.4mm [mm] "single pin connector 3.3x1.4mm"
  rect 4.3x2.4 hole 1.4 slot 3.3 at 0 deg: 1(0,0)
PowerPAK_SO-8L [mm] "based on Vishay recommended land pattern Document 63818 Feb 7, 2012"
  rect 1x0.41 smd: 1(-2.805,1.905) 2(-2.805,0.635) 3(-2.805,-0.635) 4(-2.805,-1.905)
  rect 3.63x4.061 smd: 5(0.805,0)
  Top Layer region: 2.615,-2.5 3.125,-2.5 3.125,2.5 2.615,2.5
  Top Layer region: -0.297,-2.64 0.298,-2.64 0.298,-2.03 -0.297,-2.03
  Top Layer region: -0.298,2.03 0.297,2.03 0.297,2.64 -0.298,2.64
  body extent -3.07,-2.57 3.08,2.57, height 1.21
PZS0100A-MFG [mm] "Recommended Land Pattern"
  rrect50% 1.35x0.2 smd paste+0 mask+0: 1(-6.675,4.8) 2(-6.675,4.4) 3(-6.675,4) 4(-6.675,3.6) 5(-6.675,3.2) 6(-6.675,2.8) 7(-6.675,2.4) 8(-6.675,2) 9(-6.675,1.6) 10(-6.675,1.2) 11(-6.675,0.8) 12(-6.675,0.4) 13(-6.675,0) 14(-6.675,-0.4) 15(-6.675,-0.8) 16(-6.675,-1.2) 17(-6.675,-1.6) 18(-6.675,-2) 19(-6.675,-2.4) 20(-6.675,-2.8) 21(-6.675,-3.2) 22(-6.675,-3.6) 23(-6.675,-4) 24(-6.675,-4.4) 25(-6.675,-4.8) 51(6.675,-4.8) 52(6.675,-4.4) 53(6.675,-4) 54(6.675,-3.6) 55(6.675,-3.2) 56(6.675,-2.8) 57(6.675,-2.4) 58(6.675,-2) 59(6.675,-1.6) 60(6.675,-1.2) 61(6.675,-0.8) 62(6.675,-0.4) 63(6.675,0) 64(6.675,0.4) 65(6.675,0.8) 66(6.675,1.2) 67(6.675,1.6) 68(6.675,2) 69(6.675,2.4) 70(6.675,2.8) 71(6.675,3.2) 72(6.675,3.6) 73(6.675,4) 74(6.675,4.4) 75(6.675,4.8)
  rrect50% 0.2x1.35 smd paste+0 mask+0: 26(-4.8,-6.675) 27(-4.4,-6.675) 28(-4,-6.675) 29(-3.6,-6.675) 30(-3.2,-6.675) 31(-2.8,-6.675) 32(-2.4,-6.675) 33(-2,-6.675) 34(-1.6,-6.675) 35(-1.2,-6.675) 36(-0.8,-6.675) 37(-0.4,-6.675) 38(0,-6.675) 39(0.4,-6.675) 40(0.8,-6.675) 41(1.2,-6.675) 42(1.6,-6.675) 43(2,-6.675) 44(2.4,-6.675) 45(2.8,-6.675) 46(3.2,-6.675) 47(3.6,-6.675) 48(4,-6.675) 49(4.4,-6.675) 50(4.8,-6.675) 76(4.8,6.675) 77(4.4,6.675) 78(4,6.675) 79(3.6,6.675) 80(3.2,6.675) 81(2.8,6.675) 82(2.4,6.675) 83(2,6.675) 84(1.6,6.675) 85(1.2,6.675) 86(0.8,6.675) 87(0.4,6.675) 88(0,6.675) 89(-0.4,6.675) 90(-0.8,6.675) 91(-1.2,6.675) 92(-1.6,6.675) 93(-2,6.675) 94(-2.4,6.675) 95(-2.8,6.675) 96(-3.2,6.675) 97(-3.6,6.675) 98(-4,6.675) 99(-4.4,6.675) 100(-4.8,6.675)
  rrect1% 10x10 smd paste-1000 mask-1000: 101(0,0)
  silkscreen extent -6.8,-6.05 6.05,6.05, body extent -7.01,-7.01 7.01,7.01, height 1.2
RGE0024T-MFG [mm]
  rrect40% 0.6x0.25 smd paste+0 mask+0: 1(-1.9,1.25) 2(-1.9,0.75) 3(-1.9,0.25) 4(-1.9,-0.25) 5(-1.9,-0.75) 6(-1.9,-1.25) 13(1.9,-1.25) 14(1.9,-0.75) 15(1.9,-0.25) 16(1.9,0.25) 17(1.9,0.75) 18(1.9,1.25)
  rrect40% 0.25x0.6 smd paste+0 mask+0: 7(-1.25,-1.9) 8(-0.75,-1.9) 9(-0.25,-1.9) 10(0.25,-1.9) 11(0.75,-1.9) 12(1.25,-1.9) 19(1.25,1.9) 20(0.75,1.9) 21(0.25,1.9) 22(-0.25,1.9) 23(-0.75,1.9) 24(-1.25,1.9)
  rrect5% 2.1x2.1 smd paste-1000 mask+0: 25(0,0)
  silkscreen extent -2.9,-2.05 2.05,2.05, body extent -2.3,-2.3 2.3,2.3, height 0.25
RGZ0048N-MFG [mm] "Recommended Land Pattern"
  rrect40% 0.6x0.25 smd paste+0 mask+0: 1(-3.4,2.75) 2(-3.4,2.25) 3(-3.4,1.75) 4(-3.4,1.25) 5(-3.4,0.75) 6(-3.4,0.25) 7(-3.4,-0.25) 8(-3.4,-0.75) 9(-3.4,-1.25) 10(-3.4,-1.75) 11(-3.4,-2.25) 12(-3.4,-2.75) 25(3.4,-2.75) 26(3.4,-2.25) 27(3.4,-1.75) 28(3.4,-1.25) 29(3.4,-0.75) 30(3.4,-0.25) 31(3.4,0.25) 32(3.4,0.75) 33(3.4,1.25) 34(3.4,1.75) 35(3.4,2.25) 36(3.4,2.75)
  rrect40% 0.25x0.6 smd paste+0 mask+0: 13(-2.75,-3.4) 14(-2.25,-3.4) 15(-1.75,-3.4) 16(-1.25,-3.4) 17(-0.75,-3.4) 18(-0.25,-3.4) 19(0.25,-3.4) 20(0.75,-3.4) 21(1.25,-3.4) 22(1.75,-3.4) 23(2.25,-3.4) 24(2.75,-3.4) 37(2.75,3.4) 38(2.25,3.4) 39(1.75,3.4) 40(1.25,3.4) 41(0.75,3.4) 42(0.25,3.4) 43(-0.25,3.4) 44(-0.75,3.4) 45(-1.25,3.4) 46(-1.75,3.4) 47(-2.25,3.4) 48(-2.75,3.4)
  rrect2% 5.15x5.15 smd paste-1000 mask+0: 49(0,0)
  silkscreen extent -4.37,-3.55 3.55,3.55, body extent -3.5,-3.5 3.5,3.5, height 1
